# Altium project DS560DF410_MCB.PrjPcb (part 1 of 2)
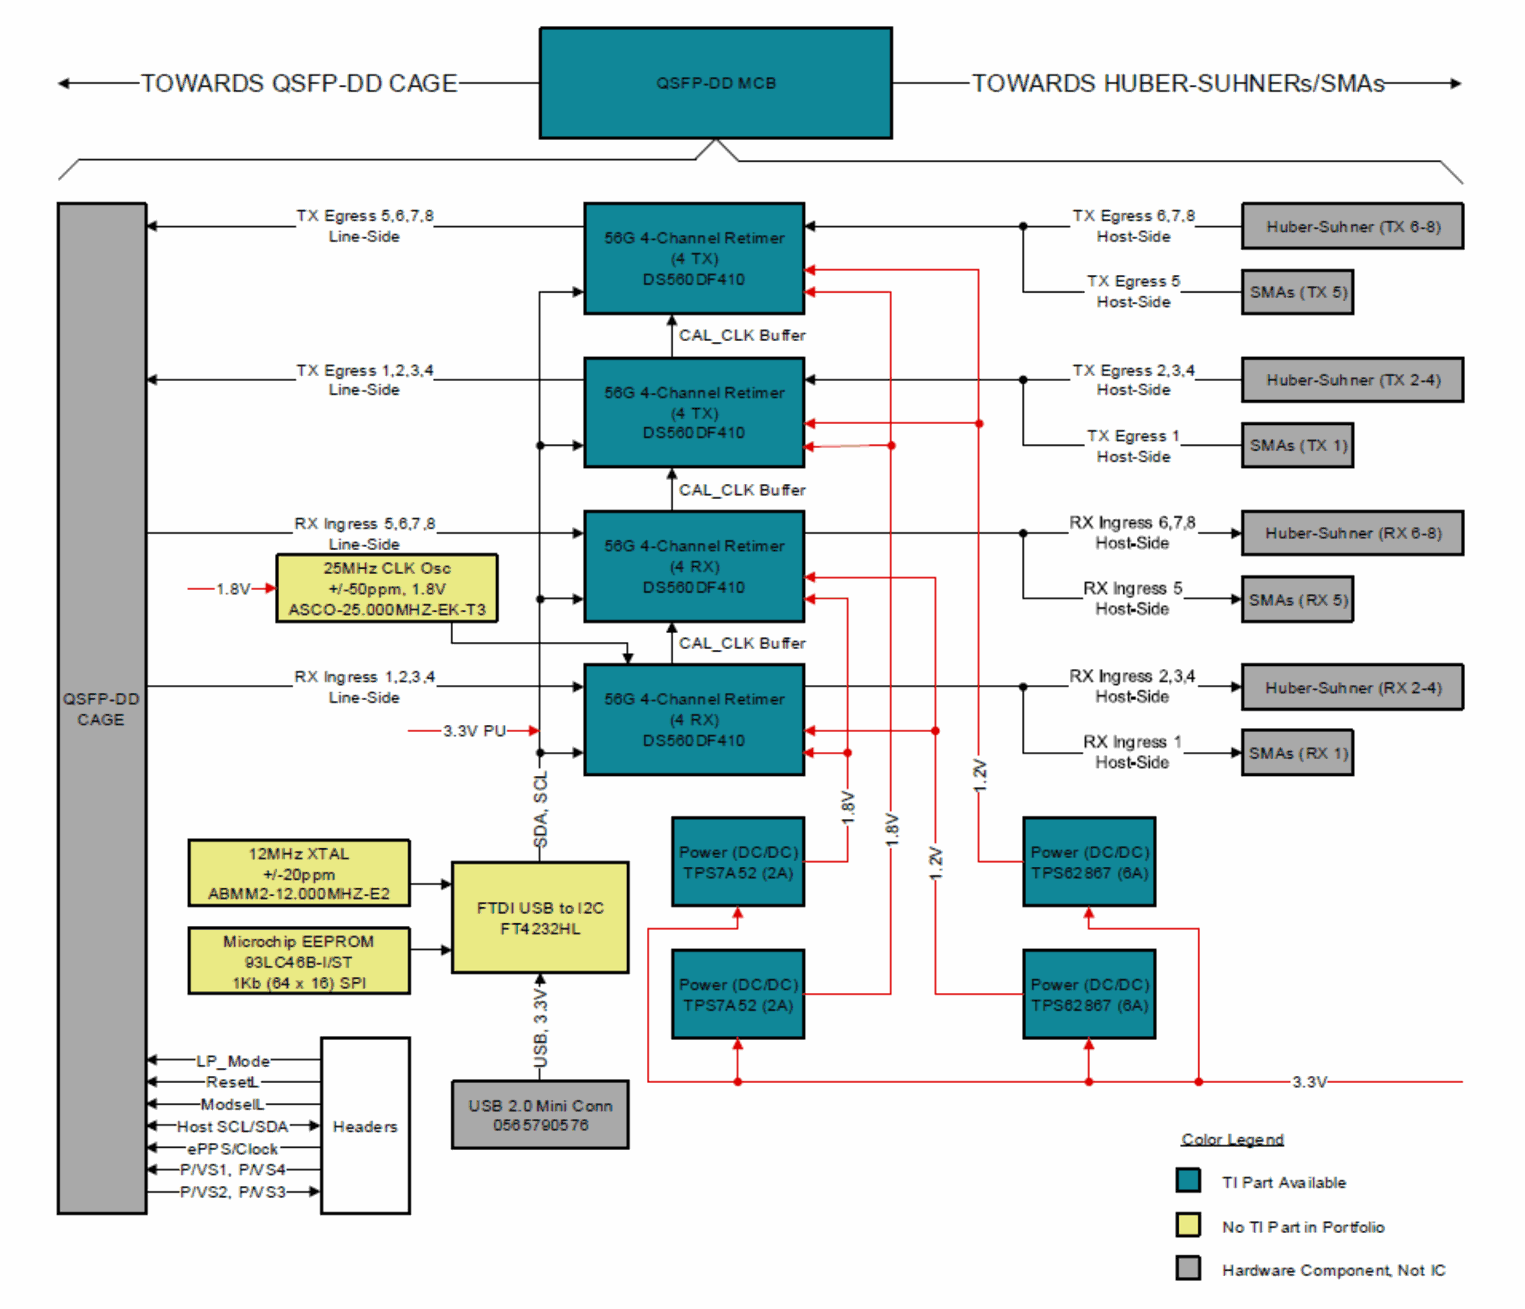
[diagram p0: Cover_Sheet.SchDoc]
CopyrightYear: 2022; PCB_Layout: TBD; PCB_Rev: E1; PRJ_Customer: Public Release; PRJ_Engineer: Lucas Wolter; PRJ_Number: TIDA-060043; PRJ_Title: 56G Retimer MCB QSFP-DD Ref Design; SCH_Rev: E1; TechSupport: http://www.ti.com/support; TID: N/A
9 sheets, 298 parts. Net scope: global (net labels, ports and power ports of the same name join across sheets).
Board file: DS560DF410_MCB_PCB_111722.PcbDoc
Sheets:
  Cover_Sheet.SchDoc
  FTDI_USB.SchDoc
  PWR_Supplies.SchDoc
  DF410_Ingress_1.SchDoc
  DF410_Ingress_2.SchDoc
  DF410_Egress_3.SchDoc
  DF410_Egress_4.SchDoc
  QSFP-DD_Connector.SchDoc
  Hardware.SchDoc

## Sheet Cover_Sheet.SchDoc: Cover Sheet
size A2; Date: Not shown in title block; ApprovedBy: Not shown in title block; CheckedBy: Not shown in title block; Author: Not shown in title block; CompanyName: Not shown in title block; Engineer: Not shown in title block; Organization: Not shown in title block; Address1: Not shown in title block; Address2: Not shown in title block; Address3: Not shown in title block; Address4: Not shown in title block; DocumentNumber: 1; Revision: Use project parameter SCH_Rev; SheetNumber: 1; SheetTotal: 1; PageSetup: Record=PageOptions¦CenterHorizontal=True¦CenterVertical=True¦PrintScale=0.69¦XCorrection=1.00¦YCorrection=1.00¦PrintKind=0¦BorderSize=5000000¦LeftOffset=0¦BottomOffset=0¦Orientation=2¦PaperLength=1000¦PaperWidth=1000¦Scale=100¦PaperSource=15¦PrintQuality=600¦MediaType=1¦DitherType=10¦PaperKind=Letter¦PrintScaleMode=1

## Sheet FTDI_USB.SchDoc: FTDI Chip, USB
size A2; Date: Not shown in title block; ApprovedBy: Not shown in title block; CheckedBy: Not shown in title block; Author: Not shown in title block; CompanyName: Not shown in title block; Engineer: Not shown in title block; Organization: Not shown in title block; Address1: Not shown in title block; Address2: Not shown in title block; Address3: Not shown in title block; Address4: Not shown in title block; DocumentNumber: 1; Revision: Use project parameter SCH_Rev; SheetNumber: 1; SheetTotal: 1; PageSetup: Record=PageOptions¦CenterHorizontal=True¦CenterVertical=True¦PrintScale=0.69¦XCorrection=1.00¦YCorrection=1.00¦PrintKind=0¦BorderSize=5000000¦LeftOffset=0¦BottomOffset=0¦Orientation=2¦PaperLength=1000¦PaperWidth=1000¦Scale=100¦PaperSource=15¦PrintQuality=600¦MediaType=1¦DitherType=10¦PaperKind=Letter¦PrintScaleMode=1
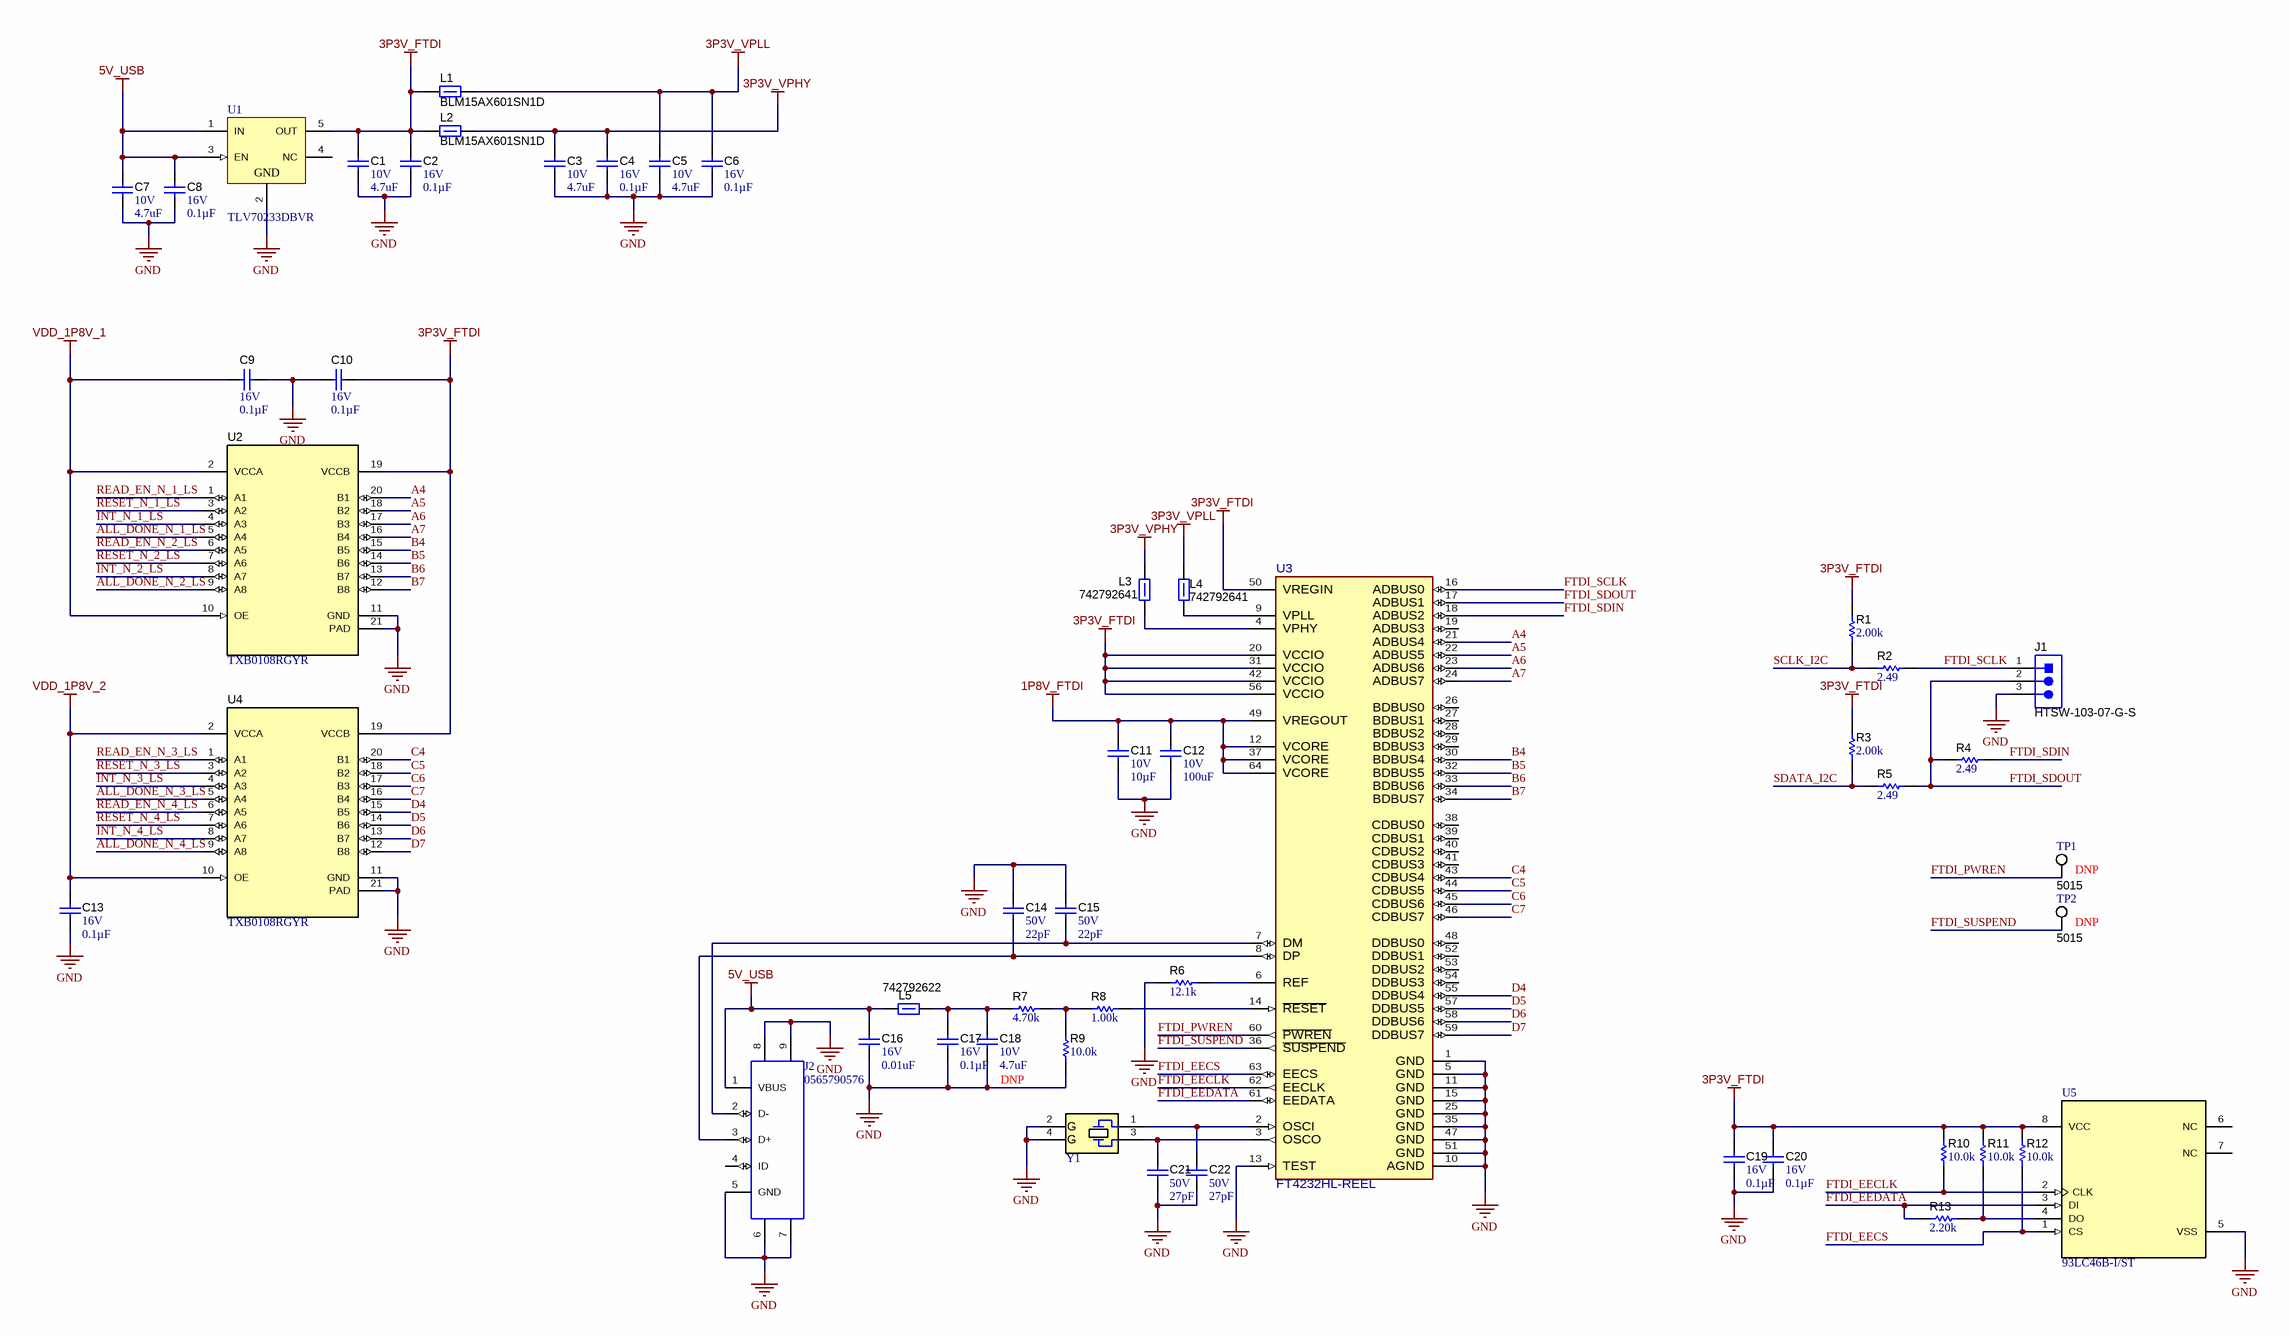
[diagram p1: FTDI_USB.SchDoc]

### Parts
C1  VDC_V: 10V  ValueDisplayed: 4.7uF  [0402_065]  (hidden comment: C1005X5R1A475K050BC)
C2  VDC_V: 16V  ValueDisplayed: 0.1µF  [0402]  (hidden comment: EMK105B7104KV-F)
C3  VDC_V: 10V  ValueDisplayed: 4.7uF  [0402_065]  (hidden comment: C1005X5R1A475K050BC)
C4  VDC_V: 16V  ValueDisplayed: 0.1µF  [0402]  (hidden comment: EMK105B7104KV-F)
C5  VDC_V: 10V  ValueDisplayed: 4.7uF  [0402_065]  (hidden comment: C1005X5R1A475K050BC)
C6  VDC_V: 16V  ValueDisplayed: 0.1µF  [0402]  (hidden comment: EMK105B7104KV-F)
C7  VDC_V: 10V  ValueDisplayed: 4.7uF  [0402_065]  (hidden comment: C1005X5R1A475K050BC)
C8  VDC_V: 16V  ValueDisplayed: 0.1µF  [0402]  (hidden comment: EMK105B7104KV-F)
C9  VDC_V: 16V  ValueDisplayed: 0.1µF  [0402]  (hidden comment: EMK105B7104KV-F)
C10  VDC_V: 16V  ValueDisplayed: 0.1µF  [0402]  (hidden comment: EMK105B7104KV-F)
C11  VDC_V: 10V  ValueDisplayed: 10µF  [0402_090]  (hidden comment: CL05A106MP8NUB8)
C12  VDC_V: 10V  ValueDisplayed: 100uF  [1206_190]  (hidden comment: C3216X5R1A107M160AC)
C13  VDC_V: 16V  ValueDisplayed: 0.1µF  [0402]  (hidden comment: EMK105B7104KV-F)
C14  VDC_V: 50V  ValueDisplayed: 22pF  [0402]  (hidden comment: GRM1555C1H220JA01D)
C15  VDC_V: 50V  ValueDisplayed: 22pF  [0402]  (hidden comment: GRM1555C1H220JA01D)
C16  VDC_V: 16V  ValueDisplayed: 0.01uF  [0402]  (hidden comment: GRM155R61C103KA01D)
C17  VDC_V: 16V  ValueDisplayed: 0.1µF  [0402]  (hidden comment: EMK105B7104KV-F)
C18  VDC_V: 10V  ValueDisplayed: 4.7uF  [0402_065]  (hidden comment: C1005X5R1A475K050BC)
C19  VDC_V: 16V  ValueDisplayed: 0.1µF  [0402]  (hidden comment: EMK105B7104KV-F)
C20  VDC_V: 16V  ValueDisplayed: 0.1µF  [0402]  (hidden comment: EMK105B7104KV-F)
C21  VDC_V: 50V  ValueDisplayed: 27pF  [0402]  (hidden comment: GJM1555C1H270JB01)
C22  VDC_V: 50V  ValueDisplayed: 27pF  [0402]  (hidden comment: GJM1555C1H270JB01)
J1  HTSW-103-07-G-S  [Samtec_HTSW-103-07-G-S]
J2  0565790576  [Molex_0565790576]
L1  BLM15AX601SN1D  [0402]
L2  BLM15AX601SN1D  [0402]
L3  742792641  [0603]
L4  742792641  [0603]
L5  742792622  [0603]
R1  ValueDisplayed: 2.00k  [0402]  (hidden comment: ERJ-2RKF2001X)
R2  ValueDisplayed: 2.49  [0402]  (hidden comment: CRCW04022R49FKED)
R3  ValueDisplayed: 2.00k  [0402]  (hidden comment: ERJ-2RKF2001X)
R4  ValueDisplayed: 2.49  [0402]  (hidden comment: CRCW04022R49FKED)
R5  ValueDisplayed: 2.49  [0402]  (hidden comment: CRCW04022R49FKED)
R6  ValueDisplayed: 12.1k  [0402]  (hidden comment: CRCW040212K1FKED)
R7  ValueDisplayed: 4.70k  [0402]  (hidden comment: ERJ-2RKF4701X)
R8  ValueDisplayed: 1.00k  [0402]  (hidden comment: CRCW04021K00FKED)
R9  ValueDisplayed: 10.0k  [0402]  (hidden comment: PCF0402-12-10K0BT1)
R10  ValueDisplayed: 10.0k  [0402]  (hidden comment: PCF0402-12-10K0BT1)
R11  ValueDisplayed: 10.0k  [0402]  (hidden comment: PCF0402-12-10K0BT1)
R12  ValueDisplayed: 10.0k  [0402]  (hidden comment: PCF0402-12-10K0BT1)
R13  ValueDisplayed: 2.20k  [0402]  (hidden comment: ERA2AEB222X)
TP1  5015  [Testpoint_Keystone_Miniature]
TP2  5015  [Testpoint_Keystone_Miniature]
U1  TLV70233DBVR  [DBV0005A_N]
U2  TXB0108RGYR  [RGY0020A]
U3  FT4232HL-REEL  [FP-FT4232HL-REEL_LQFP64-MFG]
U4  TXB0108RGYR  [RGY0020A]
U5  93LC46B-I/ST  [TSSOP-8]
Y1  ABMM2-12.000MHZ-E2-T  [Abracon_ABMM2]  (value not drawn)

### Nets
1P8V_FTDI: C11.1 C12.1 U3.12(VCORE) U3.37(VCORE) U3.49(VREGOUT) U3.64(VCORE)
3P3V_FTDI: C1.1 C2.1 C10.2 C19.1 C20.1 L1.1 L2.1 R1.2 R3.2 R10.2 R11.2 R12.2 U1.5(OUT) U2.19(VCCB) U3.20(VCCIO) U3.31(VCCIO) U3.42(VCCIO) U3.50(VREGIN) U3.56(VCCIO) U4.19(VCCB) U5.8(VCC)
3P3V_VPHY: C3.1 C4.1 L2.2 L3.2
3P3V_VPLL: C5.1 C6.1 L1.2 L4.2
5V_USB: C7.1 C8.1 C16.1 J2.1(VBUS) L5.1 U1.1(IN) U1.3(EN)
GND: C1.2 C2.2 C3.2 C4.2 C5.2 C6.2 C7.2 C8.2 C9.2 C10.1 C11.2 C12.2 C13.1 C14.1 C15.1 C16.2 C17.2 C18.2 C19.2 C20.2 C21.2 C22.2 J1.3 J2.5(GND) J2.6 J2.7 J2.8 J2.9 R6.1 R9.1 U1.2(GND) U2.11(GND) U2.21(PAD) U3.1(GND) U3.5(GND) U3.10(AGND) U3.11(GND) U3.13(TEST) U3.15(GND) U3.25(GND) U3.35(GND) U3.47(GND) U3.51(GND) U4.11(GND) U4.21(PAD) U5.5(VSS) Y1.2(GND) Y1.4(GND)
VDD_1P8V_1: C9.1 U2.2(VCCA) U2.10(OE)
VDD_1P8V_2: C13.2 U4.2(VCCA) U4.10(OE)
A4: U2.20(B1) U3.21(ADBUS4)
A5: U2.18(B2) U3.22(ADBUS5)
A6: U2.17(B3) U3.23(ADBUS6)
A7: U2.16(B4) U3.24(ADBUS7)
ALL_DONE_N_1_LS: U2.5(A4)
ALL_DONE_N_2_LS: U2.9(A8)
ALL_DONE_N_3_LS: U4.5(A4)
ALL_DONE_N_4_LS: U4.9(A8)
B4: U2.15(B5) U3.30(BDBUS4)
B5: U2.14(B6) U3.32(BDBUS5)
B6: U2.13(B7) U3.33(BDBUS6)
B7: U2.12(B8) U3.34(BDBUS7)
C4: U3.43(CDBUS4) U4.20(B1)
C5: U3.44(CDBUS5) U4.18(B2)
C6: U3.45(CDBUS6) U4.17(B3)
C7: U3.46(CDBUS7) U4.16(B4)
D4: U3.55(DDBUS4) U4.15(B5)
D5: U3.57(DDBUS5) U4.14(B6)
D6: U3.58(DDBUS6) U4.13(B7)
D7: U3.59(DDBUS7) U4.12(B8)
FTDI_EECLK: R10.1 U3.62(EECLK) U5.2(CLK)
FTDI_EECS: R12.1 U3.63(EECS) U5.1(CS)
FTDI_EEDATA: R13.1 U3.61(EEDATA) U5.3(DI)
FTDI_PWREN: TP1.1 U3.60(~{PWREN})
FTDI_SCLK: J1.1 R2.2 U3.16(ADBUS0)
FTDI_SDIN: R4.2 U3.18(ADBUS2)
FTDI_SDOUT: J1.2 R4.1 R5.2 U3.17(ADBUS1)
FTDI_SUSPEND: TP2.1 U3.36(~{SUSPEND})
INT_N_1_LS: U2.4(A3)
INT_N_2_LS: U2.8(A7)
INT_N_3_LS: U4.4(A3)
INT_N_4_LS: U4.8(A7)
READ_EN_N_1_LS: U2.1(A1)
READ_EN_N_2_LS: U2.6(A5)
READ_EN_N_3_LS: U4.1(A1)
READ_EN_N_4_LS: U4.6(A5)
RESET_N_1_LS: U2.3(A2)
RESET_N_2_LS: U2.7(A6)
RESET_N_3_LS: U4.3(A2)
RESET_N_4_LS: U4.7(A6)
SCLK_I2C: R1.1 R2.1
SDATA_I2C: R3.1 R5.1
NetC14_2: C14.2 J2.3(D+) U3.8(DP)
NetC15_2: C15.2 J2.2(D-) U3.7(DM)
NetC17_1: C17.1 C18.1 L5.2 R7.1
NetC21_1: C21.1 U3.3(OSCO) Y1.3
NetC22_1: C22.1 U3.2(OSCI) Y1.1
NetL3_1: L3.1 U3.4(VPHY)
NetL4_1: L4.1 U3.9(VPLL)
NetR6_2: R6.2 U3.6(REF)
NetR7_2: R7.2 R8.1 R9.2
NetR8_2: R8.2 U3.14(~{RESET})
NetR11_1: R11.1 R13.2 U5.4(DO)

Not connected (* = marked no-connect by the designer): J2 4(ID); U1 4(NC); U3 19(ADBUS3) 26(BDBUS0) 27(BDBUS1) 28(BDBUS2) 29(BDBUS3) 38(CDBUS0) 39(CDBUS1) 40(CDBUS2) 41(CDBUS3) 48(DDBUS0) 52(DDBUS1) 53(DDBUS2) 54(DDBUS3); U5 6(NC) 7(NC)

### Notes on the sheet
- (near TP1) DNP
- (near TP2) DNP
- (near C18) DNP

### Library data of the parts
C1 C3 C5 C7 C18 = CMP-0006268-2: CAP, CERM, 4.7 uF, 10 V, +/- 10%, X5R, 0402; Manufacturer: TDK; TaMin_C: -55°C; ESR_ohm: 3.417m; Polarized: N; SizeAreaWB_mm2: 3; Value1: 0.003417 ohm; U/M: EA; Value: 4.7uF; TaMax_C: 85°C; SizeZ_mm: 0.65; SizeX_mm: 1; SizeY_mm: 0.5; Cap_F: 4.7µF; IRMS_A: 2.7063A; AEC Category: Q200
C2 C4 C6 C8-C10 C13 C17 C19 C20 = CMP-0860188-1: CAP, CERM, 0.1 µF, 16 V,+/- 10%, X7R, 0402; Manufacturer: Taiyo Yuden; TaMin_C: -55°C; Polarized: N; SizeAreaWB_mm2: 3; U/M: EA; Value: 0.1uF; TaMax_C: 125°C; SizeZ_mm: 0.6; SizeX_mm: 1; SizeY_mm: 0.5; Cap_F: 100nF; AEC Category: Q200
C11 = CMP-0084009-1: CAP, CERM, 10 µF, 10 V,+/- 20%, X5R, 0402; Manufacturer: Samsung Electro-Mechanics; TaMin_C: -55°C; ESR_ohm: 1m; Polarized: N; Green_Lifecycle: Active; SizeAreaWB_mm2: 3; Green_REACh: Passed; Value1: 0.001 ohm; U/M: EA; Value: 10uF; TaMax_C: 85°C; SizeZ_mm: 0.9; SizeX_mm: 1; SizeY_mm: 0.5; Cap_Case: 0402; AEC Category: Q200
C12 = CMP-0008649-2: CAP, CERM, 100 uF, 10 V, +/- 20%, X5R, 1206_190; Manufacturer: TDK; TaMin_C: -55°C; ESR_ohm: 2.838m; Polarized: N; SizeAreaWB_mm2: 10.92; Value1: 0.002838 ohm; U/M: EA; Value: 100uF; TaMax_C: 85°C; SizeZ_mm: 1.9; SizeX_mm: 3.2; SizeY_mm: 1.6; SizeArea_mm2: 5.12; Cap_F: 100µF; IRMS_A: 4.3069A; AEC Category: Q200
C14 C15 = CMP-0006439-2: CAP, CERM, 22 pF, 50 V, +/- 5%, C0G/NP0, 0402; Manufacturer: MuRata; TaMin_C: -55°C; Polarized: N; SizeAreaWB_mm2: 3; Value1: Unknown; U/M: EA; Value: 22pF; TaMax_C: 125°C; SizeZ_mm: 0.6; SizeX_mm: 1; SizeY_mm: 0.5; AEC Category: Q200
C16 = CMP-0006590-2: CAP, CERM, 0.01 uF, 16 V, +/- 10%, X5R, 0402; Manufacturer: MuRata; TaMin_C: -55°C; Polarized: N; SizeAreaWB_mm2: 3; Value1: Unknown; U/M: EA; Value: 0.01uF; TaMax_C: 85°C; SizeZ_mm: 0.6; SizeX_mm: 1; SizeY_mm: 0.5; Cap_F: 10nF; AEC Category: Q200
C21 C22 = CMP-0006365-2: CAP, CERM, 27 pF, 50 V, +/- 5%, C0G/NP0, 0402; Manufacturer: MuRata; TaMin_C: -55°C; Polarized: N; SizeAreaWB_mm2: 3; Value1: Unknown; U/M: EA; Value: 27pF; TaMax_C: 125°C; SizeZ_mm: 0.6; SizeX_mm: 1; SizeY_mm: 0.5; AEC Category: Q200
J1 = CMP-0075484-1: Header, 100mil, 3x1, Gold, TH; Manufacturer: Samtec; Green_REACh: Passed; CT: False; Green_Lifecycle: Active; CNHeader: True
J2 = CMP-0079047-2: Receptacle, USB Mini-AB, 0.8mm, 5x1, Gold, R/A, SMT; Manufacturer: Molex; Cert_UL: Y; Gender: Female; Pitch_mm: 0.8; Row_Count: 1; Current_A: 1A; Voltage_V: 30V
L1 L2 = CMP-0003317-1: Ferrite Bead, 600 ohm @ 100 MHz, 0.5 A, 0402; Manufacturer: MuRata; ZTyp@100MHz_Ohm: 600; SizeAreaWB_mm2: 3; DCR_ohm: 0.34; Value1: 0.34 ohm; Value: 600 ohm; Imax_A: 500mA; SizeZ_mm: 0.6; SizeX_mm: 1; SizeY_mm: 0.5; Value2: 0.5A
L3 L4 = CMP-0003192-2: Ferrite Bead, 300 ohm @ 100 MHz, 2 A, 0603; Manufacturer: Wurth Elektronik; Ztyp@1GHz_Ohm: 273.989; ZTyp@100MHz_Ohm: 300; SizeAreaWB_mm2: 4.68; DCR_ohm: 0.15; Value1: 0.15 ohm; Value: 300 ohm; Imax_A: 2A; SizeZ_mm: 1; SizeX_mm: 1.6; SizeY_mm: 0.8; SizeArea_mm2: 1.28
L5 = CMP-0003185-2: Ferrite Bead, 180 ohm @ 100 MHz, 0.5 A, 0603; Manufacturer: Wurth Elektronik; Ztyp@1GHz_Ohm: 190.577; ZTyp@100MHz_Ohm: 180; SizeAreaWB_mm2: 4.68; DCR_ohm: 0.3; Value1: 0.3 ohm; Value: 180 ohm; Imax_A: 500mA; SizeZ_mm: 1; SizeX_mm: 1.6; SizeY_mm: 0.8; Value2: 0.5A; SizeArea_mm2: 1.28
R1 R3 = CMP-0026676-1: RES, 2.00 k, 1%, 0.1 W, AEC-Q200 Grade 0, 0402; Manufacturer: Panasonic; Power_W: 100mW; TempCo: 100 ppm/C; Value_Code: 2k00; U/M: EA; Value: 2.00k; EIA_Code: E96; Res_ohm: 2k; SizeX_mm: 1; SizeY_mm: 0.5; SizeZ_mm: 0.6; Value2: 0.1W; AEC Qualified: Y; VDC_V: 50V; AEC Grade: 0; AEC Category: Q200
R2 R4 R5 = CMP-0026271-2: RES, 2.49, 1%, 0.063 W, AEC-Q200 Grade 0, 0402; Manufacturer: Vishay-Dale; Power_W: 63mW; TempCo: 100 ppm/C; Value_Code: 2R49; Value: 2.49; EIA_Code: E96; SizeX_mm: 1; SizeY_mm: 0.5; SizeZ_mm: 0.6; Value2: 0.063W; AEC Qualified: Y; VDC_V: 50V; AEC Category: Q200; AEC Grade: 0
R6 = CMP-0025991-3: RES, 12.1 k, 1%, 0.063 W, AEC-Q200 Grade 0, 0402; Manufacturer: Vishay-Dale; Power_W: 63mW; TempCo: 100 ppm/C; Value_Code: 12k1; Value: 12.1k; EIA_Code: E96; SizeX_mm: 1; SizeY_mm: 0.5; SizeZ_mm: 0.6; Value2: 0.063W; AEC Qualified: Y; VDC_V: 50V; AEC Category: Q200; AEC Grade: 0
R7 = CMP-0026700-1: RES, 4.70 k, 1%, 0.1 W, 0402; Manufacturer: Panasonic; Power_W: 100mW; TempCo: 100 ppm/C; Value_Code: 4k70; U/M: EA; Value: 4.70k; Res_ohm: 4.7k; SizeX_mm: 1; SizeY_mm: 0.5; SizeZ_mm: 0.6; Value2: 0.1W; VDC_V: 50V; AEC Category: Q200
R8 = CMP-0026071-3: RES, 1.00 k, 1%, 0.063 W, AEC-Q200 Grade 0, 0402; Manufacturer: Vishay-Dale; Power_W: 63mW; TempCo: 100 ppm/C; Value_Code: 1k00; Value: 1.00k; EIA_Code: E96; Res_ohm: 1k; SizeX_mm: 1; SizeY_mm: 0.5; SizeZ_mm: 0.6; Value2: 0.063W; AEC Qualified: Y; VDC_V: 50V; AEC Category: Q200; AEC Grade: 0
R9-R12 = CMP-0026796-1: RES, 10.0 k, 0.1%, 0.063 W, 0402; Manufacturer: TT Electronics/IRC; Power_W: 63mW; TempCo: 10 ppm/C; Value_Code: 10k0; U/M: EA; Value: 10.0k; EIA_Code: E192; Res_ohm: 10k; SizeX_mm: 1; SizeY_mm: 0.5; SizeZ_mm: 0.6; Value2: 0.063W; AEC Qualified: N; VDC_V: 25V; AEC Category: Q200
R13 = CMP-0074667-1: RES, 2.20 k, 0.1%, 0.0625 W, AEC-Q200 Grade 0, 0402; Manufacturer: Panasonic; Power_W: 62.5mW; TempCo: 25 ppm/C; Value_Code: 2k20; U/M: EA; Value: 2.20k; Res_ohm: 2.2k; SizeX_mm: 1.0; SizeY_mm: 0.5; SizeZ_mm: 0.6; AEC Qualified: Y; VDC_V: 50V; AEC Grade: 0; AEC Category: Q200
TP1 TP2 = CMP-0055152-2: Test Point, Miniature, SMT; Manufacturer: Keystone Electronics; CNHeader: FALSE; Green_Lifecycle: Active; Green_REACh: Passed; CT: TRUE
U1 = CMP-0035516-1: Single Output LDO, 300 mA, Fixed 3.3 V Output, 2 to 5.5 V Input, with Low IQ, 5-pin SOT-23 (DBV), -40 to 125 degC, Green (RoHS & no Sb/Br); Manufacturer: Texas Instruments; Fixed Output Options(V): 3.3; Vdo(Typ)(mV): 220; Accuracy(%): 2; Iq(Typ)(mA): 0.03; SubFamily: Single Channel LDO; Iout(Max)(A): 0.3; Vin(Max)(V): 5.5
U2 U4 = CMP-0074359-2: 8-Bit Bidirectional Voltage-Level Shifter with Auto Direction Sensing and +/-15-kV ESD Protect, RGY0020A (VQFN-20); Alternate Manufacturer: Texas Instruments; SizeAreaWB_mm2: 24.75; U/M: EA; SizeZ_mm: 1.0; SizeX_mm: 3.5; SizeY_mm: 4.5; SizeArea_mm2: 15.75; CompType: IC
U3 = CMP-0086897-1: IC USB HS QUAD UART/SYNC 64-LQFP; Manufacturer: FTDI; SizeZ_mm: 1.6mm
U5 = CMP-0081524-1: 1K Microwire Compatible Serial EEPROM, TSSOP-8; Manufacturer: Microchip; SizeArea_mm2: 19.2; SizeAreaWB_mm2: 42; SizeY_mm: 3; SizeZ_mm: 1.2; SizeX_mm: 6.4
Y1 = CMP-0079033-1: Crystal, 12 MHz, 20 ppm, SMD; Manufacturer: Abracon Corporation; Frequency Stability: -20 / +20 ppm; SizeAreaWB_mm2: 44.8; SizeArea_mm2: 21.6; Frequency Tolerance: 20 ppm; AEC Category: Q200; TaMax_C: 60°C; SizeZ_mm: 1.2; Frequency_Fixed: 12MHz; TaMin_C: -10°C; SizeY_mm: 6; SizeX_mm: 3.6

## Sheet PWR_Supplies.SchDoc: Power Supplies
size A2; Date: Not shown in title block; ApprovedBy: Not shown in title block; CheckedBy: Not shown in title block; Author: Not shown in title block; CompanyName: Not shown in title block; Engineer: Not shown in title block; Organization: Not shown in title block; Address1: Not shown in title block; Address2: Not shown in title block; Address3: Not shown in title block; Address4: Not shown in title block; DocumentNumber: 1; Revision: Use project parameter SCH_Rev; SheetNumber: 1; SheetTotal: 1; PageSetup: Record=PageOptions¦CenterHorizontal=True¦CenterVertical=True¦PrintScale=0.69¦XCorrection=1.00¦YCorrection=1.00¦PrintKind=0¦BorderSize=5000000¦LeftOffset=0¦BottomOffset=0¦Orientation=2¦PaperLength=1000¦PaperWidth=1000¦Scale=100¦PaperSource=15¦PrintQuality=600¦MediaType=1¦DitherType=10¦PaperKind=Letter¦PrintScaleMode=1
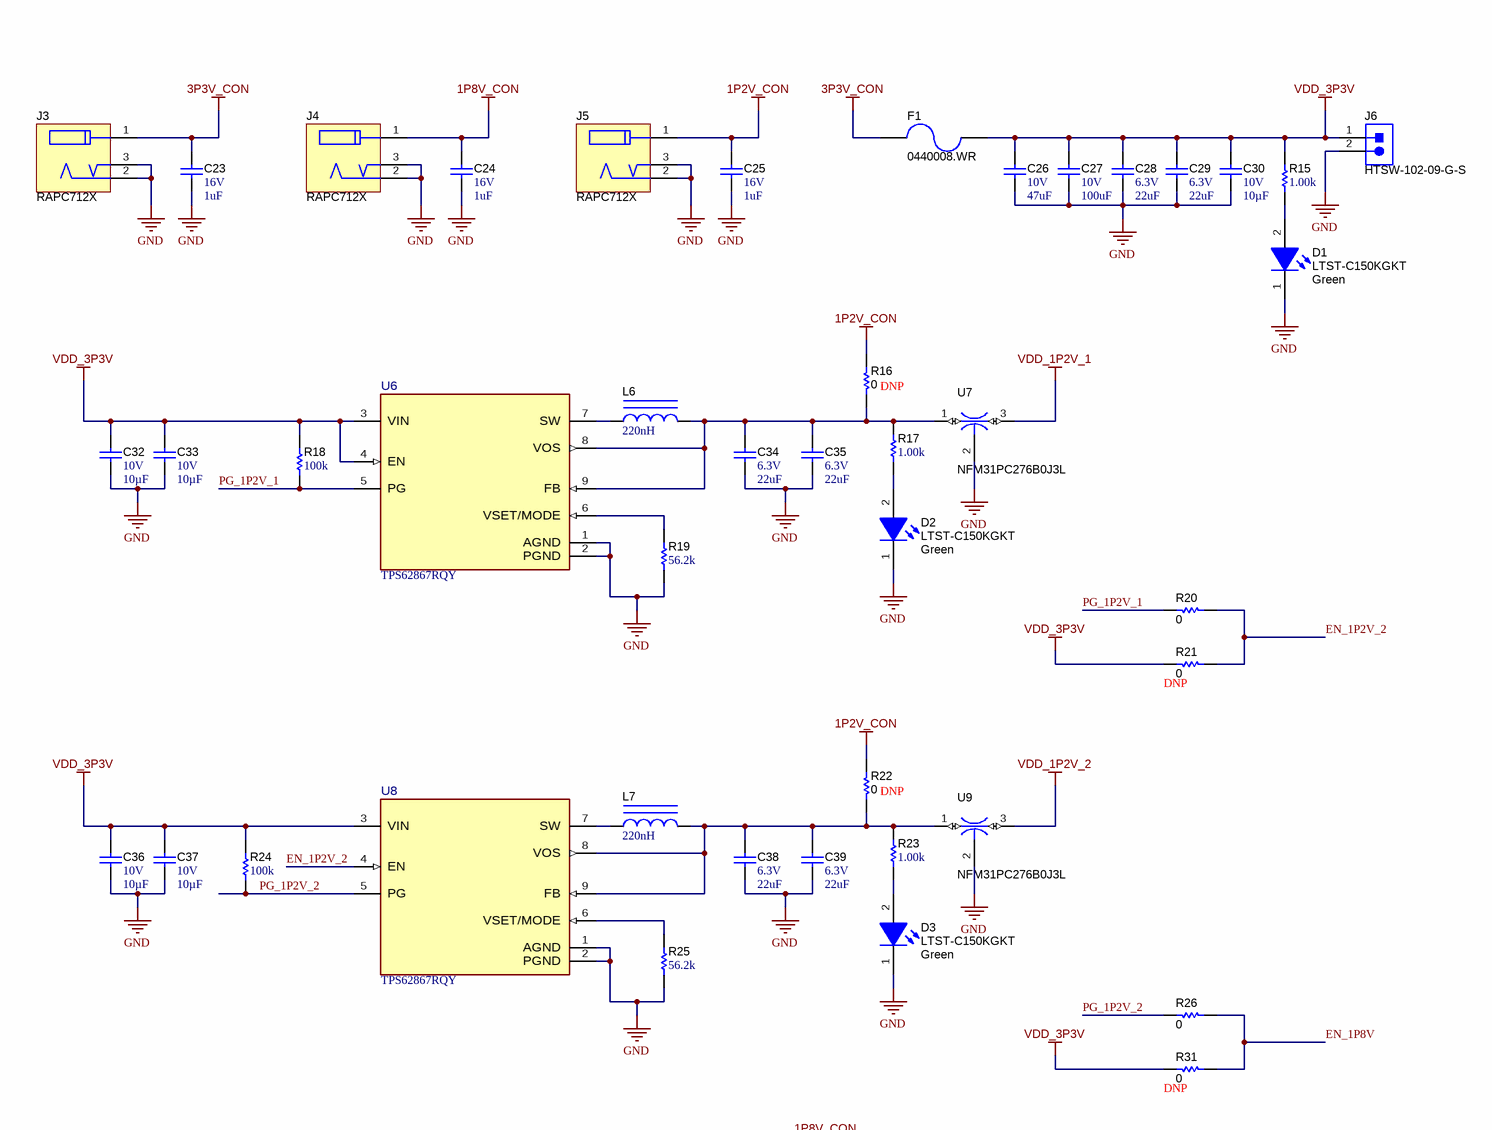
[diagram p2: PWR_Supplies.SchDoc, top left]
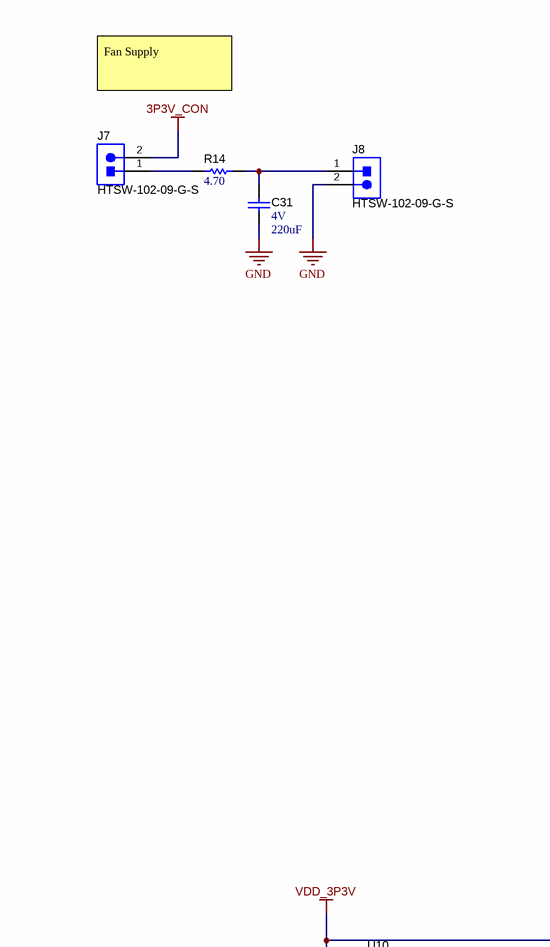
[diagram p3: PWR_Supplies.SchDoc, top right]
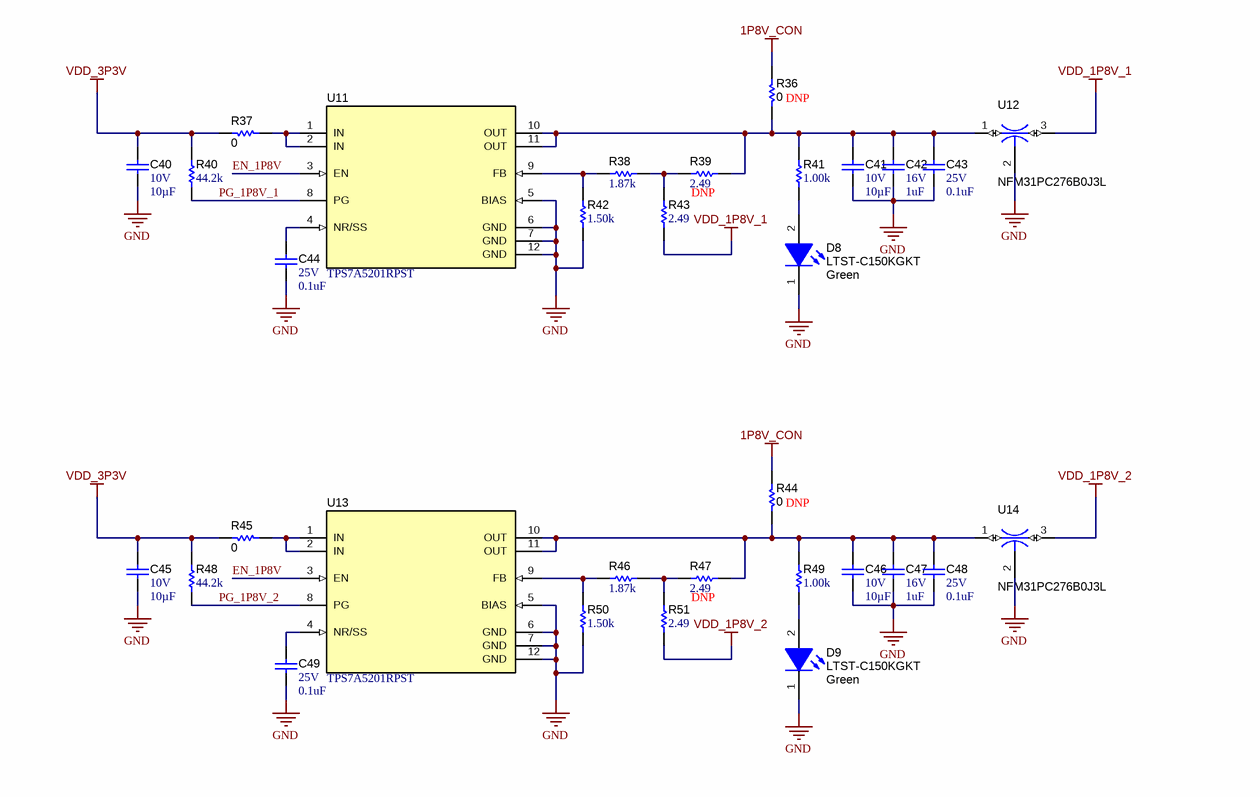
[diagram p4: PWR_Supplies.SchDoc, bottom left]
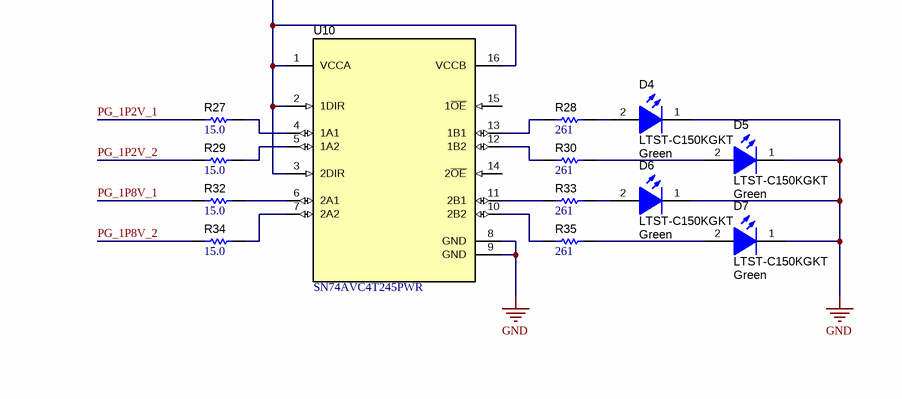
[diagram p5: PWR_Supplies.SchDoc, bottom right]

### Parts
C23  VDC_V: 16V  ValueDisplayed: 1uF  [0402]  (hidden comment: EMK105BJ105KVHF)
C24  VDC_V: 16V  ValueDisplayed: 1uF  [0402]  (hidden comment: EMK105BJ105KVHF)
C25  VDC_V: 16V  ValueDisplayed: 1uF  [0402]  (hidden comment: EMK105BJ105KVHF)
C26  VDC_V: 10V  ValueDisplayed: 47uF  [1206_180]  (hidden comment: GRT31CR61A476KE13L)
C27  VDC_V: 10V  ValueDisplayed: 100uF  [1206_190]  (hidden comment: C3216X5R1A107M160AC)
C28  VDC_V: 6.3V  ValueDisplayed: 22uF  [0402]  (hidden comment: GRM155R60J226ME11D)
C29  VDC_V: 6.3V  ValueDisplayed: 22uF  [0402]  (hidden comment: GRM155R60J226ME11D)
C30  VDC_V: 10V  ValueDisplayed: 10µF  [0402_090]  (hidden comment: CL05A106MP8NUB8)
C31  VDC_V: 4V  ValueDisplayed: 220uF  [1206_190]  (hidden comment: GRM31CR60G227ME11L)
C32  VDC_V: 10V  ValueDisplayed: 10µF  [0402_090]  (hidden comment: CL05A106MP8NUB8)
C33  VDC_V: 10V  ValueDisplayed: 10µF  [0402_090]  (hidden comment: CL05A106MP8NUB8)
C34  VDC_V: 6.3V  ValueDisplayed: 22uF  [0402]  (hidden comment: GRM155R60J226ME11D)
C35  VDC_V: 6.3V  ValueDisplayed: 22uF  [0402]  (hidden comment: GRM155R60J226ME11D)
C36  VDC_V: 10V  ValueDisplayed: 10µF  [0402_090]  (hidden comment: CL05A106MP8NUB8)
C37  VDC_V: 10V  ValueDisplayed: 10µF  [0402_090]  (hidden comment: CL05A106MP8NUB8)
C38  VDC_V: 6.3V  ValueDisplayed: 22uF  [0402]  (hidden comment: GRM155R60J226ME11D)
C39  VDC_V: 6.3V  ValueDisplayed: 22uF  [0402]  (hidden comment: GRM155R60J226ME11D)
C40  VDC_V: 10V  ValueDisplayed: 10µF  [0402_090]  (hidden comment: CL05A106MP8NUB8)
C41  VDC_V: 10V  ValueDisplayed: 10µF  [0402_090]  (hidden comment: CL05A106MP8NUB8)
C42  VDC_V: 16V  ValueDisplayed: 1uF  [0402]  (hidden comment: EMK105BJ105KVHF)
C43  VDC_V: 25V  ValueDisplayed: 0.1uF  [0402]  (hidden comment: GRM155R71E104KE14D)
C44  VDC_V: 25V  ValueDisplayed: 0.1uF  [0402]  (hidden comment: GRM155R71E104KE14D)
C45  VDC_V: 10V  ValueDisplayed: 10µF  [0402_090]  (hidden comment: CL05A106MP8NUB8)
C46  VDC_V: 10V  ValueDisplayed: 10µF  [0402_090]  (hidden comment: CL05A106MP8NUB8)
C47  VDC_V: 16V  ValueDisplayed: 1uF  [0402]  (hidden comment: EMK105BJ105KVHF)
C48  VDC_V: 25V  ValueDisplayed: 0.1uF  [0402]  (hidden comment: GRM155R71E104KE14D)
C49  VDC_V: 25V  ValueDisplayed: 0.1uF  [0402]  (hidden comment: GRM155R71E104KE14D)
D1  LTST-C150KGKT  value Green  [LTST-C150_1206_Green]
D2  LTST-C150KGKT  value Green  [LTST-C150_1206_Green]
D3  LTST-C150KGKT  value Green  [LTST-C150_1206_Green]
D4  LTST-C150KGKT  value Green  [LTST-C150_1206_Green]
D5  LTST-C150KGKT  value Green  [LTST-C150_1206_Green]
D6  LTST-C150KGKT  value Green  [LTST-C150_1206_Green]
D7  LTST-C150KGKT  value Green  [LTST-C150_1206_Green]
D8  LTST-C150KGKT  value Green  [LTST-C150_1206_Green]
D9  LTST-C150KGKT  value Green  [LTST-C150_1206_Green]
F1  0440008.WR  [1206]
J3  RAPC712X  [CONN_RAPC712X]
J4  RAPC712X  [CONN_RAPC712X]
J5  RAPC712X  [CONN_RAPC712X]
J6  HTSW-102-09-G-S  [Samtec_HTSW-102-09-x-S]
J7  HTSW-102-09-G-S  [Samtec_HTSW-102-09-x-S]
J8  HTSW-102-09-G-S  [Samtec_HTSW-102-09-x-S]
L6  ValueDisplayed: 220nH  [744373210022]  (hidden comment: 744373210022)
L7  ValueDisplayed: 220nH  [744373210022]  (hidden comment: 744373210022)
R14  ValueDisplayed: 4.70  [0201]  (hidden comment: RC0201FR-074R7L)
R15  ValueDisplayed: 1.00k  [0402]  (hidden comment: MCR01MZPF1001)
R16  ValueDisplayed: 0  [0402]  (hidden comment: ERJ-2GE0R00X)
R17  ValueDisplayed: 1.00k  [0402]  (hidden comment: MCR01MZPF1001)
R18  ValueDisplayed: 100k  [0402]  (hidden comment: RC0402FR-07100KL)
R19  ValueDisplayed: 56.2k  [0402]  (hidden comment: CRCW040256K2FKED)
R20  ValueDisplayed: 0  [0402]  (hidden comment: ERJ-2GE0R00X)
R21  ValueDisplayed: 0  [0402]  (hidden comment: ERJ-2GE0R00X)
R22  ValueDisplayed: 0  [0402]  (hidden comment: ERJ-2GE0R00X)
R23  ValueDisplayed: 1.00k  [0402]  (hidden comment: MCR01MZPF1001)
R24  ValueDisplayed: 100k  [0402]  (hidden comment: RC0402FR-07100KL)
R25  ValueDisplayed: 56.2k  [0402]  (hidden comment: CRCW040256K2FKED)
R26  ValueDisplayed: 0  [0402]  (hidden comment: ERJ-2GE0R00X)
R27  ValueDisplayed: 15.0  [0402]  (hidden comment: CRCW040215R0FKED)
R28  ValueDisplayed: 261  [0402]  (hidden comment: CRCW0402261RFKED)
R29  ValueDisplayed: 15.0  [0402]  (hidden comment: CRCW040215R0FKED)
R30  ValueDisplayed: 261  [0402]  (hidden comment: CRCW0402261RFKED)
R31  ValueDisplayed: 0  [0402]  (hidden comment: ERJ-2GE0R00X)
R32  ValueDisplayed: 15.0  [0402]  (hidden comment: CRCW040215R0FKED)
R33  ValueDisplayed: 261  [0402]  (hidden comment: CRCW0402261RFKED)
R34  ValueDisplayed: 15.0  [0402]  (hidden comment: CRCW040215R0FKED)
R35  ValueDisplayed: 261  [0402]  (hidden comment: CRCW0402261RFKED)
R36  ValueDisplayed: 0  [0402]  (hidden comment: ERJ-2GE0R00X)
R37  ValueDisplayed: 0  [0402]  (hidden comment: ERJ-2GE0R00X)
R38  ValueDisplayed: 1.87k  [0402]  (hidden comment: RC0402FR-071K87L)
R39  ValueDisplayed: 2.49  [0402]  (hidden comment: CRCW04022R49FKED)
R40  ValueDisplayed: 44.2k  [0402]  (hidden comment: CRCW040244K2FKED)
R41  ValueDisplayed: 1.00k  [0402]  (hidden comment: MCR01MZPF1001)
R42  ValueDisplayed: 1.50k  [0402]  (hidden comment: CRCW04021K50FKED)
R43  ValueDisplayed: 2.49  [0402]  (hidden comment: CRCW04022R49FKED)
R44  ValueDisplayed: 0  [0402]  (hidden comment: ERJ-2GE0R00X)
R45  ValueDisplayed: 0  [0402]  (hidden comment: ERJ-2GE0R00X)
R46  ValueDisplayed: 1.87k  [0402]  (hidden comment: RC0402FR-071K87L)
R47  ValueDisplayed: 2.49  [0402]  (hidden comment: CRCW04022R49FKED)
R48  ValueDisplayed: 44.2k  [0402]  (hidden comment: CRCW040244K2FKED)
R49  ValueDisplayed: 1.00k  [0402]  (hidden comment: MCR01MZPF1001)
R50  ValueDisplayed: 1.50k  [0402]  (hidden comment: CRCW04021K50FKED)
R51  ValueDisplayed: 2.49  [0402]  (hidden comment: CRCW04022R49FKED)
U6  TPS62867RQY  [RQY0009A-MFG]
U7  NFM31PC276B0J3L  [Murata_NFM31P]
U8  TPS62867RQY  [RQY0009A-MFG]
U9  NFM31PC276B0J3L  [Murata_NFM31P]
U10  SN74AVC4T245PWR  [PW0016A_N]
U11  TPS7A5201RPST  [RPS0012A]
U12  NFM31PC276B0J3L  [Murata_NFM31P]
U13  TPS7A5201RPST  [RPS0012A]
U14  NFM31PC276B0J3L  [Murata_NFM31P]

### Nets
1P2V_CON: C25.1 J5.1 R16.2 R22.2
1P8V_CON: C24.1 J4.1 R36.2 R44.2
3P3V_CON: C23.1 F1.2 J3.1 J7.2
GND: C23.2 C24.2 C25.2 C26.2 C27.2 C28.2 C29.2 C30.2 C31.2 C32.2 C33.2 C34.2 C35.2 C36.2 C37.2 C38.2 C39.2 C40.2 C41.2 C42.2 C43.2 C44.2 C45.2 C46.2 C47.2 C48.2 C49.2 D1.1(K) D2.1(K) D3.1(K) D4.1(K) D5.1(K) D6.1(K) D7.1(K) D8.1(K) D9.1(K) J3.2 J3.3 J4.2 J4.3 J5.2 J5.3 J6.2 J8.2 R19.1 R25.1 R42.1 R50.1 U6.1(AGND) U6.2(PGND) U7.2 U8.1(AGND) U8.2(PGND) U9.2 U10.8(GND) U10.9(GND) U11.5(BIAS) U11.6(GND) U11.7(GND) U11.12(GND) U12.2 U13.5(BIAS) U13.6(GND) U13.7(GND) U13.12(GND) U14.2
VDD_1P2V_1: U7.3
VDD_1P2V_2: U9.3
VDD_1P8V_1: R43.1 U12.3
VDD_1P8V_2: R51.1 U14.3
VDD_3P3V: C26.1 C27.1 C28.1 C29.1 C30.1 C32.1 C33.1 C36.1 C37.1 C40.1 C45.1 F1.1 J6.1 R15.2 R18.2 R21.1 R24.2 R31.1 R37.1 R40.2 R45.1 R48.2 U6.3(VIN) U6.4(EN) U8.3(VIN) U10.1(VCCA) U10.2(1DIR) U10.3(2DIR) U10.16(VCCB)
EN_1P2V_2: R20.2 R21.2 U8.4(EN)
EN_1P8V: R26.2 R31.2 U11.3(EN) U13.3(EN)
PG_1P2V_1: R18.1 R20.1 R27.1 U6.5(PG)
PG_1P2V_2: R24.1 R26.1 R29.1 U8.5(PG)
PG_1P8V_1: R32.1 R40.1 U11.8(PG)
PG_1P8V_2: R34.1 R48.1 U13.8(PG)
NetC31_1: C31.1 J8.1 R14.2
NetC34_1: C34.1 C35.1 L6.2 R16.1 R17.2 U6.8(VOS) U6.9(FB) U7.1
NetC38_1: C38.1 C39.1 L7.2 R22.1 R23.2 U8.8(VOS) U8.9(FB) U9.1
NetC41_1: C41.1 C42.1 C43.1 R36.1 R39.2 R41.2 U11.10(OUT) U11.11(OUT) U12.1
NetC44_1: C44.1 U11.4(NR/SS)
NetC46_1: C46.1 C47.1 C48.1 R44.1 R47.2 R49.2 U13.10(OUT) U13.11(OUT) U14.1
NetC49_1: C49.1 U13.4(NR/SS)
NetD1_2: D1.2(A) R15.1
NetD2_2: D2.2(A) R17.1
NetD3_2: D3.2(A) R23.1
NetD4_2: D4.2(A) R28.2
NetD5_2: D5.2(A) R30.2
NetD6_2: D6.2(A) R33.2
NetD7_2: D7.2(A) R35.2
NetD8_2: D8.2(A) R41.1
NetD9_2: D9.2(A) R49.1
NetJ7_1: J7.1 R14.1
NetL6_1: L6.1 U6.7(SW)
NetL7_1: L7.1 U8.7(SW)
NetR19_2: R19.2 U6.6(VSET/MODE)
NetR25_2: R25.2 U8.6(VSET/MODE)
NetR27_2: R27.2 U10.4(1A1)
NetR28_1: R28.1 U10.13(1B1)
NetR29_2: R29.2 U10.5(1A2)
NetR30_1: R30.1 U10.12(1B2)
NetR32_2: R32.2 U10.6(2A1)
NetR33_1: R33.1 U10.11(2B1)
NetR34_2: R34.2 U10.7(2A2)
NetR35_1: R35.1 U10.10(2B2)
NetR37_2: R37.2 U11.1(IN) U11.2(IN)
NetR38_1: R38.1 R42.2 U11.9(FB)
NetR38_2: R38.2 R39.1 R43.2
NetR45_2: R45.2 U13.1(IN) U13.2(IN)
NetR46_1: R46.1 R50.2 U13.9(FB)
NetR46_2: R46.2 R47.1 R51.2

Not connected (* = marked no-connect by the designer): U10 14(2~{OE}) 15(1~{OE})

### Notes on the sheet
- Fan Supply
- (near R16) DNP
- (near R21) DNP
- (near R22) DNP
- (near R31) DNP
- (near R36) DNP
- (near R39) DNP
- (near R44) DNP
- (near R47) DNP

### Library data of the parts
C23-C25 C42 C47 = CMP-0006347-2: CAP, CERM, 1 uF, 16 V, +/- 10%, X5R, 0402; Manufacturer: Taiyo Yuden; TaMin_C: -55°C; Polarized: N; SizeAreaWB_mm2: 3; Value1: Unknown; U/M: EA; Value: 1uF; TaMax_C: 85°C; SizeZ_mm: 0.6; SizeX_mm: 1; SizeY_mm: 0.5; Cap_F: 1µF; AEC Category: Q200
C26 = CMP-0009013-2: CAP, CERM, 47 uF, 10 V, +/- 10%, X5R, AEC-Q200 Grade 1, 1206; Manufacturer: MuRata; TaMin_C: -55°C; Polarized: N; SizeAreaWB_mm2: 10.92; Value1: Unknown; U/M: EA; Value: 47uF; TaMax_C: 85°C; SizeZ_mm: 1.8; SizeX_mm: 3.2; SizeY_mm: 1.6; Cap_Case: 1206; SizeArea_mm2: 5.12; AEC Qualified: Y; Cap_F: 47µF; AEC Grade: 1; AEC Category: Q200
C27 = CMP-0008649-2: as C12 on sheet FTDI_USB
C28 C29 C34 C35 C38 C39 = CMP-0006545-2: CAP, CERM, 22 uF, 6.3 V, +/- 20%, X5R, 0402; Manufacturer: MuRata; TaMin_C: -55°C; Polarized: N; SizeAreaWB_mm2: 3; Value1: Unknown; U/M: EA; Value: 22uF; TaMax_C: 85°C; SizeZ_mm: 0.6; SizeY_mm: 0.5; SizeX_mm: 1; Cap_F: 22µF; AEC Category: Q200
C30 C32 C33 C36 C37 C40 C41 C45 C46 = CMP-0084009-1: as C11 on sheet FTDI_USB
C31 = CMP-0008932-2: CAP, CERM, 220 uF, 4 V, +/- 20%, X5R, 1206_190; Manufacturer: MuRata; TaMin_C: -55°C; Polarized: N; SizeAreaWB_mm2: 10.92; Value1: Unknown; U/M: EA; Value: 220uF; TaMax_C: 85°C; SizeZ_mm: 1.9; SizeX_mm: 3.2; SizeY_mm: 1.6; Cap_Case: 1206; SizeArea_mm2: 5.12; Cap_F: 220µF; AEC Category: Q200
C43 C44 C48 C49 = CMP-0006659-2: CAP, CERM, 0.1 uF, 25 V, +/- 10%, X7R, 0402; Manufacturer: MuRata; TaMin_C: -55°C; Polarized: N; SizeAreaWB_mm2: 3; Value1: Unknown; U/M: EA; Value: 0.1uF; TaMax_C: 125°C; SizeZ_mm: 0.6; SizeX_mm: 1; SizeY_mm: 0.5; Cap_F: 100nF; AEC Category: Q200
D1-D9 = CMP-0002920-2: LED, Green, SMD; Manufacturer: LiteOn; Io_A: 30mA; Vr_V: 5V; Tjmax_C: 85°C; Value1: W; Angle: 130; Vf_V: 2V; Type: AlInGaP
F1 = CMP-0003460-2: Fuse, 8 A, 32VAC/VDC, SMD; Manufacturer: Littelfuse; Irating_A: 8A; SizeAreaWB_mm2: 10.92; Interrupt_AC: 50A; VAC_V: 32V; SizeZ_mm: 1.35; SizeX_mm: 3.2; SizeY_mm: 1.6; SizeArea_mm2: 5.12; Rtyp_Ohm: 6.34m; MeltingTyp: 12.95
J3-J5 = CMP-0074931-1: Power Jack, mini, 2.5mm OD, R/A, TH; Manufacturer: Switchcraft; CNHeader: False; Green_Lifecycle: Not Set; Green_REACh: Incomplete
J6-J8 = CMP-0075626-1: Header, 100mil, 2x1, Gold, TH; Manufacturer: Samtec; Pitch_mm: 2.54; Gender: Male; Cert_CSA: Y; CT: False; Row_Count: 1
L6 L7 = CMP-0059748-1: FIXED IND 220NH 7.7A 8 MOHM SMD; Manufacturer: Würth Elektronik; Isat: 8.3A @ 30% inductance drop; Irms: 7.6A @ 40C rise; Green_Lifecycle: Not Set; SizeAreaWB_mm2: 14.7; DCR_ohm: 9m; Green_REACh: Incomplete; Value1: 0.009 ohm; Material: Powdered Iron; Imax_A: 7.6A; SizeZ_mm: 1.2; SizeX_mm: 3.2; SizeY_mm: 2.5; SizeArea_mm2: 8; CompType: Inductor; AEC Qualified: N; AEC Category: Q200
R14 = CMP-0027750-1: RES, 4.70, 1%, 0.05 W, 0201; Manufacturer: Yageo America; Power_W: 50mW; TempCo: 350 ppm/C; Value_Code: 4R70; U/M: EA; Value: 4.70; Res_ohm: 4.7; SizeX_mm: 0.6; SizeY_mm: 0.3; SizeZ_mm: 0.26; Value2: 0.05W; SizeArea_mm2: 0.18; AEC Qualified: N; VDC_V: 25V; AEC Category: Q200
R15 R17 R23 R41 R49 = CMP-0026716-1: RES, 1.00 k, 1%, 0.063 W, 0402; Manufacturer: Rohm; Power_W: 63mW; TempCo: 100 ppm/C; Value_Code: 1k00; U/M: EA; Value: 1.00k; EIA_Code: E96; Res_ohm: 1k; SizeX_mm: 1; SizeY_mm: 0.5; SizeZ_mm: 0.6; Value2: 0.063W; AEC Qualified: N; VDC_V: 50V; AEC Category: Q200
R16 R20-R22 R26 R31 R36 R37 R44 R45 = CMP-0026992-3: RES, 0, 5%, 0.1 W, AEC-Q200 Grade 0, 0402; Manufacturer: Panasonic; Power_W: 100mW; TempCo: 600 ppm/C; Value_Code: 0000; Value: 0; EIA_Code: E24; SizeX_mm: 1; SizeY_mm: 0.5; SizeZ_mm: 0.6; Value2: 0.1W; AEC Qualified: Y; VDC_V: 50V; AEC Category: Q200; SizeAreaWB_mm2: 3
R18 R24 = CMP-0026721-1: RES, 100 k, 1%, 0.0625 W, 0402; Manufacturer: Yageo America; Power_W: 62.5mW; TempCo: 100 ppm/C; U/M: EA; Value: 100k; EIA_Code: E96; SizeX_mm: 1; SizeY_mm: 0.5; SizeZ_mm: 0.6; AEC Qualified: N; VDC_V: 50V; AEC Category: Q200
R19 R25 = CMP-0026453-2: RES, 56.2 k, 1%, 0.063 W, AEC-Q200 Grade 0, 0402; Manufacturer: Vishay-Dale; Power_W: 63mW; TempCo: 100 ppm/C; Value_Code: 56k2; Value: 56.2k; EIA_Code: E96; SizeX_mm: 1; SizeY_mm: 0.5; SizeZ_mm: 0.6; Value2: 0.063W; AEC Qualified: Y; VDC_V: 50V; AEC Category: Q200; AEC Grade: 0
R27 R29 R32 R34 = CMP-0026030-3: RES, 15.0, 1%, 0.063 W, AEC-Q200 Grade 0, 0402; Manufacturer: Vishay-Dale; Power_W: 63mW; TempCo: 100 ppm/C; Value_Code: 15R0; Value: 15.0; EIA_Code: E96; Res_ohm: 15; SizeX_mm: 1; SizeY_mm: 0.5; SizeZ_mm: 0.6; Value2: 0.063W; AEC Qualified: Y; VDC_V: 50V; AEC Category: Q200; AEC Grade: 0
R28 R30 R33 R35 = CMP-0026204-2: RES, 261, 1%, 0.063 W, AEC-Q200 Grade 0, 0402; Manufacturer: Vishay-Dale; Power_W: 63mW; TempCo: 100 ppm/C; Value_Code: 261R; Value: 261; EIA_Code: E96; SizeX_mm: 1; SizeY_mm: 0.5; SizeZ_mm: 0.6; Value2: 0.063W; AEC Qualified: Y; VDC_V: 50V; AEC Category: Q200; AEC Grade: 0
R38 R46 = CMP-0078783-1: RES, 1.87 k, 1%, 0.063 W, 0402; Manufacturer: Yageo America; Value_Code: 1k87; SizeArea_mm2: 0.5; AEC Qualified: N; AEC Category: Q200; Value: 1.87k; SizeZ_mm: 0.6; EIA_Code: E96; TempCo: 100 ppm/C; Power_W: 63mW; VDC_V: 50V; Value2: 0.063W; SizeX_mm: 1
R39 R43 R47 R51 = CMP-0026271-2: as R2 on sheet FTDI_USB
R40 R48 = CMP-0026383-2: RES, 44.2 k, 1%, 0.063 W, AEC-Q200 Grade 0, 0402; Manufacturer: Vishay-Dale; Power_W: 63mW; TempCo: 100 ppm/C; Value_Code: 44k2; Value: 44.2k; EIA_Code: E96; SizeX_mm: 1; SizeY_mm: 0.5; SizeZ_mm: 0.6; Value2: 0.063W; AEC Qualified: Y; VDC_V: 50V; AEC Category: Q200; AEC Grade: 0
R42 R50 = CMP-0026088-3: RES, 1.50 k, 1%, 0.063 W, AEC-Q200 Grade 0, 0402; Manufacturer: Vishay-Dale; Power_W: 63mW; TempCo: 100 ppm/C; Value_Code: 1k50; Value: 1.50k; EIA_Code: E96; Res_ohm: 1.5k; SizeX_mm: 1; SizeY_mm: 0.5; SizeZ_mm: 0.6; Value2: 0.063W; AEC Qualified: Y; VDC_V: 50V; AEC Category: Q200; AEC Grade: 0
U6 U8 = CMP-0089105-4: 2.4-V to 5.5-V Input, 6-A Step-Down Converter in 1.5-mm x 2.5-mm QFN Package; Manufacturer: Texas Instruments; SizeZ_mm: 1mm; Number Of Outputs: 1; AEC Qualified: No; Switching Topology: Buck; Switching Frequency: 2.4MHz; Output Type: Fixed,AdjustableProgrammable; CompType: IC; Max Duty Cycle: 100%; Max Supply Voltage: 5.5V; Standoff Height: 0mm; Min Supply Voltage: 2.4V; Nominal Supply Current: 4uA; TJmax_C: +125°C; AEC Category: Q200
U7 U9 U12 U14 = CMP-0001934-2: FILTER LC HIGH FREQ 27uF 1206; Manufacturer: MuRata
U10 = CMP-0066448-2: 4-Bit Dual-Supply Bus Transceiver with Configurable Voltage-Level Shifting and 3-State Outputs, PW0016A (TSSOP-16); Alternate Manufacturer: Texas Instruments; Green_Lifecycle: Active; SizeAreaWB_mm2: 58.8; Green_REACh: Passed; SizeZ_mm: 1.2; SizeX_mm: 6.4; SizeY_mm: 5.0; SizeArea_mm2: 32.0; CompType: IC; AEC Category: Q200; AEC Qualified: N
U11 U13 = CMP-0860539-1: 3-A, High-Accuracy (0.75%), Low-Noise (4.4μVRMS), LDO Voltage Regulator, RPS0012A (VQFN-12); Alternate Manufacturer: Texas Instruments; SizeZ_mm: 1; SizeX_mm: 2.2; AEC Category: Q200; CompType: IC; SizeAreaWB_mm2: 11.2; SizeY_mm: 2.5; SizeArea_mm2: 5.5; AEC Qualified: N

## Sheet DF410_Ingress_1.SchDoc: Retimer Ingress RX1-4
size A2; Date: Not shown in title block; ApprovedBy: Not shown in title block; CheckedBy: Not shown in title block; Author: Not shown in title block; CompanyName: Not shown in title block; Engineer: Not shown in title block; Organization: Not shown in title block; Address1: Not shown in title block; Address2: Not shown in title block; Address3: Not shown in title block; Address4: Not shown in title block; DocumentNumber: 1; Revision: Use project parameter SCH_Rev; SheetNumber: 1; SheetTotal: 1; PageSetup: Record=PageOptions¦CenterHorizontal=True¦CenterVertical=True¦PrintScale=0.69¦XCorrection=1.00¦YCorrection=1.00¦PrintKind=0¦BorderSize=5000000¦LeftOffset=0¦BottomOffset=0¦Orientation=2¦PaperLength=1000¦PaperWidth=1000¦Scale=100¦PaperSource=15¦PrintQuality=600¦MediaType=1¦DitherType=10¦PaperKind=Letter¦PrintScaleMode=1
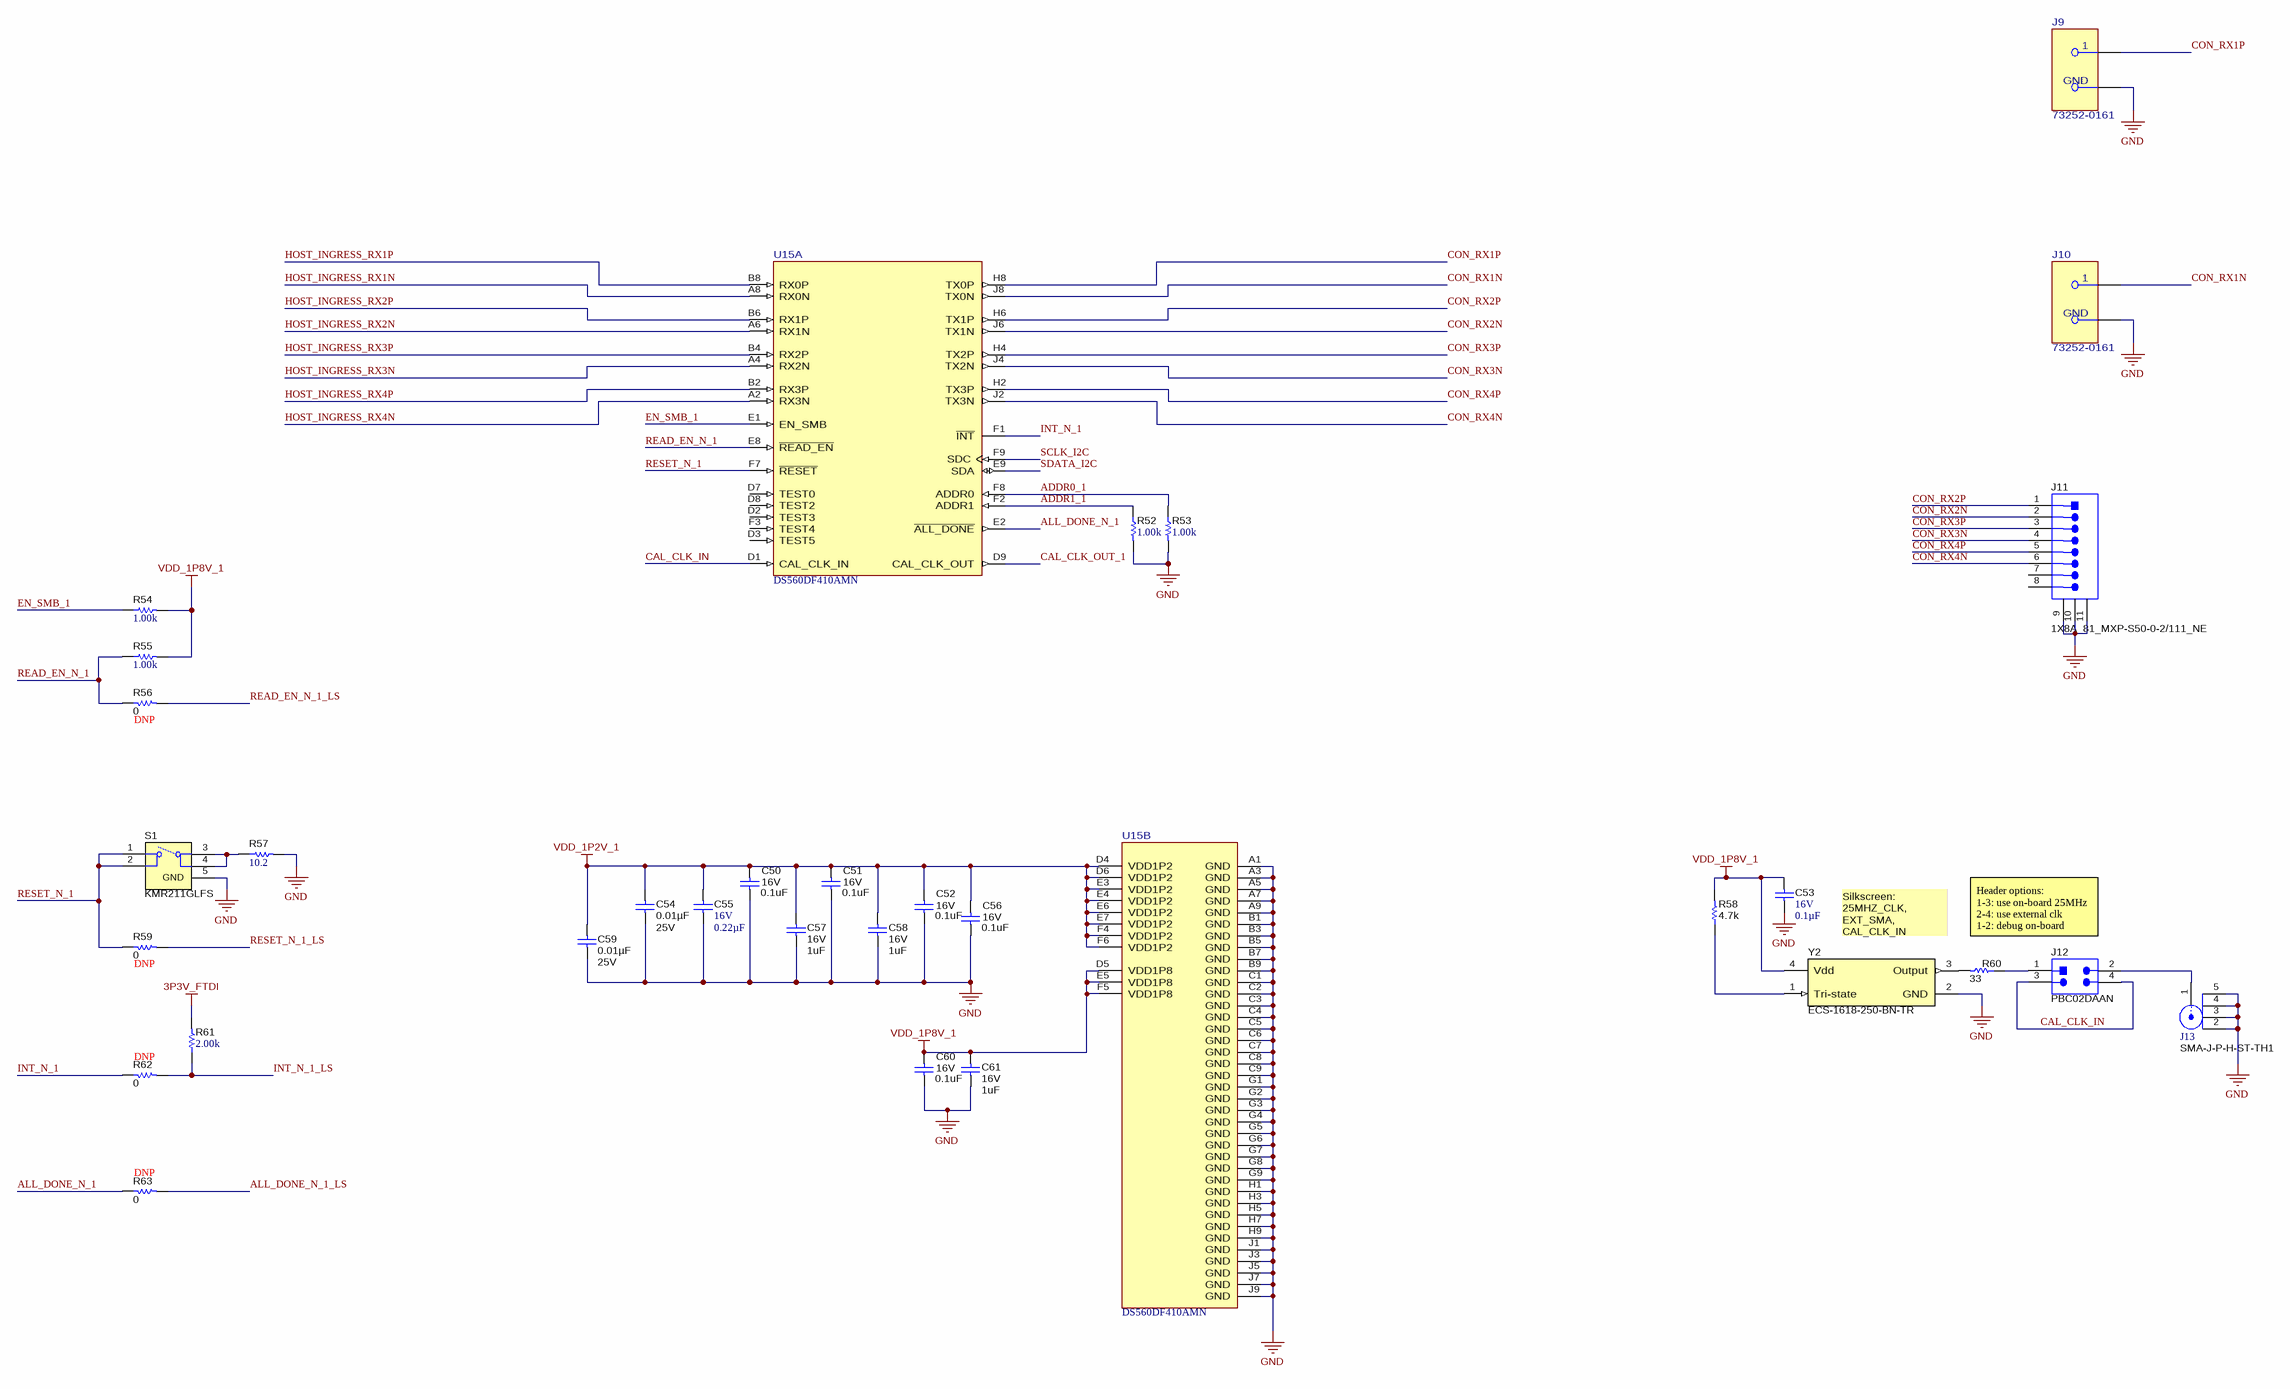
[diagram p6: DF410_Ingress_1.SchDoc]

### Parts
C50  Value2: 16V  ValueDisplayed: 0.1uF  [0201_033]  (hidden comment: GRM033C71C104KE14D)
C51  Value2: 16V  ValueDisplayed: 0.1uF  [0201_033]  (hidden comment: GRM033C71C104KE14D)
C52  Value2: 16V  ValueDisplayed: 0.1uF  [0201_033]  (hidden comment: GRM033C71C104KE14D)
C53  VDC_V: 16V  ValueDisplayed: 0.1µF  [0402]  (hidden comment: EMK105B7104KV-F)
C54  ValueDisplayed: 0.01µF  VDC_V: 25V  [0201_033]  (hidden comment: GRM033R61E103KA12D)
C55  VDC_V: 16V  ValueDisplayed: 0.22µF  [0402]  (hidden comment: CL05B224KO5NNNC)
C56  Value2: 16V  ValueDisplayed: 0.1uF  [0201_033]  (hidden comment: GRM033C71C104KE14D)
C57  VDC_V: 16V  ValueDisplayed: 1uF  [0603]  (hidden comment: GRM188R61C105KA93D)
C58  VDC_V: 16V  ValueDisplayed: 1uF  [0603]  (hidden comment: GRM188R61C105KA93D)
C59  ValueDisplayed: 0.01µF  VDC_V: 25V  [0201_033]  (hidden comment: GRM033R61E103KA12D)
C60  Value2: 16V  ValueDisplayed: 0.1uF  [0201_033]  (hidden comment: GRM033C71C104KE14D)
C61  VDC_V: 16V  ValueDisplayed: 1uF  [0603]  (hidden comment: GRM188R61C105KA93D)
J9  73252-0161  [FP-73252-0161_CONN_RF_JACK-MFG]
J10  73252-0161  [FP-73252-0161_CONN_RF_JACK-MFG]
J11  1X8A_81_MXP-S50-0-2/111_NE  [H+S_1x8A_81_MXP-S50-0-2_111N]
J12  PBC02DAAN  [Sullins_PxC02DAAN]
J13  SMA-J-P-H-ST-TH1  [SAMTEC_SMA-J-P-H-ST-TH1]
R52  ValueDisplayed: 1.00k  [0402]  (hidden comment: CRCW04021K00FKED)
R53  ValueDisplayed: 1.00k  [0402]  (hidden comment: CRCW04021K00FKED)
R54  ValueDisplayed: 1.00k  [0402]  (hidden comment: CRCW04021K00FKED)
R55  ValueDisplayed: 1.00k  [0402]  (hidden comment: CRCW04021K00FKED)
R56  ValueDisplayed: 0  [0402]  (hidden comment: ERJ-2GE0R00X)
R57  ValueDisplayed: 10.2  [0402]  (hidden comment: CRCW040210R2FKED)
R58  ValueDisplayed: 4.7k  [0402]  (hidden comment: CRCW04024K70JNED)
R59  ValueDisplayed: 0  [0402]  (hidden comment: ERJ-2GE0R00X)
R60  value 33  [0402]  (hidden comment: Resistor)
R61  ValueDisplayed: 2.00k  [0402]  (hidden comment: ERJ-2RKF2001X)
R62  ValueDisplayed: 0  [0402]  (hidden comment: ERJ-2GE0R00X)
R63  ValueDisplayed: 0  [0402]  (hidden comment: ERJ-2GE0R00X)
S1  KMR211GLFS  [SW_KMR211GLFS]
U15  DS560DF410AMN  [AMN0081A-MFG]  (parts A,B of 2)
Y2  ECS-1618-250-BN-TR  [ECS-1618-250-BN-TR]

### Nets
3P3V_FTDI: R61.2
GND: C50.2 C51.2 C52.2 C53.2 C54.2 C55.2 C56.2 C57.2 C58.2 C59.2 C60.2 C61.2 J9.2(GND) J10.2(GND) J11.9 J11.10 J11.11 J13.2 J13.3 J13.4 J13.5 R52.2 R53.2 R57.2 S1.5(GND) U15.A1(GND) U15.A3(GND) U15.A5(GND) U15.A7(GND) U15.A9(GND) U15.B1(GND) U15.B3(GND) U15.B5(GND) U15.B7(GND) U15.B9(GND) U15.C1(GND) U15.C2(GND) U15.C3(GND) U15.C4(GND) U15.C5(GND) U15.C6(GND) U15.C7(GND) U15.C8(GND) U15.C9(GND) U15.G1(GND) U15.G2(GND) U15.G3(GND) U15.G4(GND) U15.G5(GND) U15.G6(GND) U15.G7(GND) U15.G8(GND) U15.G9(GND) U15.H1(GND) U15.H3(GND) U15.H5(GND) U15.H7(GND) U15.H9(GND) U15.J1(GND) U15.J3(GND) U15.J5(GND) U15.J7(GND) U15.J9(GND) Y2.2(GND)
VDD_1P2V_1: C50.1 C51.1 C52.1 C54.1 C55.1 C56.1 C57.1 C58.1 C59.1 U15.D4(VDD1P2) U15.D6(VDD1P2) U15.E3(VDD1P2) U15.E4(VDD1P2) U15.E6(VDD1P2) U15.E7(VDD1P2) U15.F4(VDD1P2) U15.F6(VDD1P2)
VDD_1P8V_1: C53.1 C60.1 C61.1 R54.2 R55.2 R58.2 U15.D5(VDD1P8) U15.E5(VDD1P8) U15.F5(VDD1P8) Y2.4(Vdd)
ADDR0_1: R53.1 U15.F8(ADDR0)
ADDR1_1: R52.1 U15.F2(ADDR1)
ALL_DONE_N_1: R63.1 U15.E2(~{ALL_DONE})
ALL_DONE_N_1_LS: R63.2
CAL_CLK_IN: J12.3 J12.4 U15.D1(CAL_CLK_IN)
CAL_CLK_OUT_1: U15.D9(CAL_CLK_OUT)
CON_RX1N: J10.1 U15.J8(TX0N)
CON_RX1P: J9.1 U15.H8(TX0P)
CON_RX2N: J11.2 U15.J6(TX1N)
CON_RX2P: J11.1 U15.H6(TX1P)
CON_RX3N: J11.4 U15.J4(TX2N)
CON_RX3P: J11.3 U15.H4(TX2P)
CON_RX4N: J11.6 U15.J2(TX3N)
CON_RX4P: J11.5 U15.H2(TX3P)
EN_SMB_1: R54.1 U15.E1(EN_SMB)
HOST_INGRESS_RX1N: U15.A8(RX0N)
HOST_INGRESS_RX1P: U15.B8(RX0P)
HOST_INGRESS_RX2N: U15.A6(RX1N)
HOST_INGRESS_RX2P: U15.B6(RX1P)
HOST_INGRESS_RX3N: U15.A4(RX2N)
HOST_INGRESS_RX3P: U15.B4(RX2P)
HOST_INGRESS_RX4N: U15.A2(RX3N)
HOST_INGRESS_RX4P: U15.B2(RX3P)
INT_N_1: R62.1 U15.F1(~{INT})
INT_N_1_LS: R61.1 R62.2
READ_EN_N_1: R55.1 R56.1 U15.E8(~{READ_EN})
READ_EN_N_1_LS: R56.2
RESET_N_1: R59.1 S1.1 S1.2 U15.F7(~{RESET})
RESET_N_1_LS: R59.2
SCLK_I2C: U15.F9(SDC)
SDATA_I2C: U15.E9(SDA)
NetJ12_1: J12.1 R60.1
NetJ12_2: J12.2 J13.1
NetR57_1: R57.1 S1.3 S1.4
NetR58_1: R58.1 Y2.1(Tri-state)
NetR60_2: R60.2 Y2.3(Output)

Not connected (* = marked no-connect by the designer): J11 7 8; U15 D2(TEST3) D3(TEST5) D7(TEST0) D8(TEST2) F3(TEST4)

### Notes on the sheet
- (near R56) DNP
- (near R59) DNP
- Silkscreen: 25MHZ_CLK, EXT_SMA, CAL_CLK_IN
- Header options:
  1-3: use on-board 25MHz
  2-4: use external clk
  1-2: debug on-board 25MHz
- (near R62) DNP
- (near R63) DNP

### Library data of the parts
C50-C52 C56 C60 = CMP-0009670-3: CAP, CERM, 0.1 uF, 16 V, +/- 10%, X5R, 0201; Manufacturer: MuRata; TaMin_C: -55°C; Polarized: N; SizeAreaWB_mm2: 2.08; Value1: Unknown; U/M: EA; Value: 0.1uF; TaMax_C: 125°C; SizeZ_mm: 0.33; SizeX_mm: 0.6; SizeY_mm: 0.3; Cap_Case: 0201; SizeArea_mm2: 0.18; Cap_F: 100nF; AEC Category: Q200
C53 = CMP-0860188-1: as C2 on sheet FTDI_USB
C54 C59 = CMP-0086060-1: CAP, CERM, 0.01 µF, 25 V,+/- 10%, X5R, 0201; Manufacturer: MuRata; SizeY_mm: 0.3; SizeZ_mm: 0.33; SizeAreaWB_mm2: 2.08; U/M: EA; AEC Category: Q200; SizeX_mm: 0.6; TaMin_C: -55°C; Polarized: N; TaMax_C: 85°C; Value: 0.01uF; Cap_F: 10nF; SizeArea_mm2: 0.18; Cap_Case: 0201
C55 = CMP-0860563-1: CAP, CERM, 0.22 µF, 16 V,+/- 10%, X7R, 0402; Manufacturer: Samsung Electro-Mechanics; TaMin_C: -55°C; Polarized: N; SizeAreaWB_mm2: 3; U/M: EA; Value: 0.22uF; TaMax_C: 125°C; SizeZ_mm: 0.6; SizeX_mm: 1; SizeY_mm: 0.5; Cap_F: 220nF; AEC Category: Q200; Green_Lifecycle: Active; Green_REACh: Incomplete
C57 C58 C61 = CMP-0007335-5: CAP, CERM, 1 uF, 16 V, +/- 10%, X5R, 0603; Manufacturer: MuRata; TaMin_C: -55°C; Polarized: N; SizeAreaWB_mm2: 4.68; Value1: Unknown; U/M: EA; Value: 1uF; TaMax_C: 85°C; SizeZ_mm: 1; SizeX_mm: 1.6; SizeY_mm: 0.8; SizeArea_mm2: 1.28; Cap_F: 1µF; AEC Category: Q200
J9 J10 = CMP-0097248-1: 2.92MM JACK,PCB,COMPRESSION W/SL; Manufacturer: Molex; Is Female: yes; Conn Orientation: Vertical; Dielectric Material: PTFE; ContactFinish: Gold,Nickel; SizeZ_mm: 11.17mm; AEC Qualified: No
J11 = CMP-0074975-2: Straight PCB plug Pin-in-hole/SMT; Manufacturer: Huber+Suhner; CT: False; Green_REACh: Incomplete; Green_Lifecycle: Not Set
J12 = CMP-0054598-1: Header, 2.54mm, 2x2, Gold, TH; Manufacturer: Sullins Connector Solutions; CNHeader: TRUE; Current_A: 3A; Shrouded: N; Gender: Male; Voltage_V: 1.8kV; Row_Count: 2; RowSpacing_mm: 2.54; CT: FALSE; Cert_UL: Y
J13 = CMP-0075495-1: SMA Jack, Straight, 50 Ohm, Gold, TH; Manufacturer: Samtec; Green_REACh: Incomplete; CT: True; Green_Lifecycle: Not Set; CNHeader: False
R52-R55 = CMP-0026071-3: as R8 on sheet FTDI_USB
R56 R59 R62 R63 = CMP-0026992-3: as R16 on sheet PWR_Supplies
R57 = CMP-0025964-3: RES, 10.2, 1%, 0.063 W, AEC-Q200 Grade 0, 0402; Manufacturer: Vishay-Dale; Power_W: 63mW; TempCo: 100 ppm/C; Value_Code: 10R2; Value: 10.2; EIA_Code: E96; SizeX_mm: 1; SizeY_mm: 0.5; SizeZ_mm: 0.6; Value2: 0.063W; AEC Qualified: Y; VDC_V: 50V; AEC Category: Q200; AEC Grade: 0
R58 = CMP-0026938-5: RES, 4.7 k, 5%, 0.063 W, AEC-Q200 Grade 0, 0402; Manufacturer: Vishay-Dale; Power_W: 63mW; TempCo: 200 ppm/C; Value_Code: 4k70; Value: 4.7k; EIA_Code: E24; SizeX_mm: 1; SizeY_mm: 0.5; SizeZ_mm: 0.6; Value2: 0.063W; AEC Qualified: Y; VDC_V: 50V; AEC Category: Q200; AEC Grade: 0
R60 = CMP-0026908-3: RES, 33, 5%, 0.063 W, AEC-Q200 Grade 0, 0402; PartNumber: CRCW040233R0JNED; Manufacturer: Vishay-Dale; Value_Code: 33R0; Power_W: 63mW; Value2: 0.063W; VDC_V: 50V; TempCo: 200 ppm/C; EIA_Code: E24; AEC Category: Q200; AEC Grade: 0; AEC Qualified: Y; SizeArea_mm2: 0.5; SizeX_mm: 1; SizeZ_mm: 0.6
R61 = CMP-0026676-1: as R1 on sheet FTDI_USB
S1 = CMP-0002322-1: Switch, SPST-NO, Off-Mom, 0.05 A, 32 VDC, SMD; Manufacturer: C&K Components; CurrentRating_mA: 50A; PositionCount: 1; SizeX_mm: 4.6; SizeY_mm: 2.8; SizeZ_mm: 1.9; SizeArea_mm2: 12.88; VDC_V: 32V; SizeAreaWB_mm2: 21.28
U15 = CMP-0095008-2: 56 Gbps Multi-Rate 4-Channel Retimer with Crosspoint; Manufacturer: Texas Instruments; AEC Category: Q200; TaMin_C: -40°C; AEC Qualified: No; SizeZ_mm: 1.225mm; Standoff Height: 0.261mm; TJmax_C: +110°C; Data Rate: 56Gbits/s; Min Supply Voltage: 1.15V; Max Supply Voltage: 1.85V; CompType: IC; TaMax_C: +85°C; Interface: I2C,SMBus,Other
Y2 = SYM-ASCO-25.000MHZ-EK-T3: XTAL OSC XO 25.0000MHZ CMOS SMD; Manufacturer: ECS Inc.; AEC Qualified: No; Max Supply Current: 4.2mA; Min Supply Voltage: 2.97V; Frequency Stability: 50ppm; Max Supply Voltage: 3.63V; Frequency_Fixed: 25MHz; Load Capacitance: 15pF

## Sheet DF410_Ingress_2.SchDoc: Retimer Ingress RX5-8
size A2; Date: Not shown in title block; ApprovedBy: Not shown in title block; CheckedBy: Not shown in title block; Author: Not shown in title block; CompanyName: Not shown in title block; Engineer: Not shown in title block; Organization: Not shown in title block; Address1: Not shown in title block; Address2: Not shown in title block; Address3: Not shown in title block; Address4: Not shown in title block; DocumentNumber: 1; Revision: Use project parameter SCH_Rev; SheetNumber: 1; SheetTotal: 1; PageSetup: Record=PageOptions¦CenterHorizontal=True¦CenterVertical=True¦PrintScale=0.69¦XCorrection=1.00¦YCorrection=1.00¦PrintKind=0¦BorderSize=5000000¦LeftOffset=0¦BottomOffset=0¦Orientation=2¦PaperLength=1000¦PaperWidth=1000¦Scale=100¦PaperSource=15¦PrintQuality=600¦MediaType=1¦DitherType=10¦PaperKind=Letter¦PrintScaleMode=1
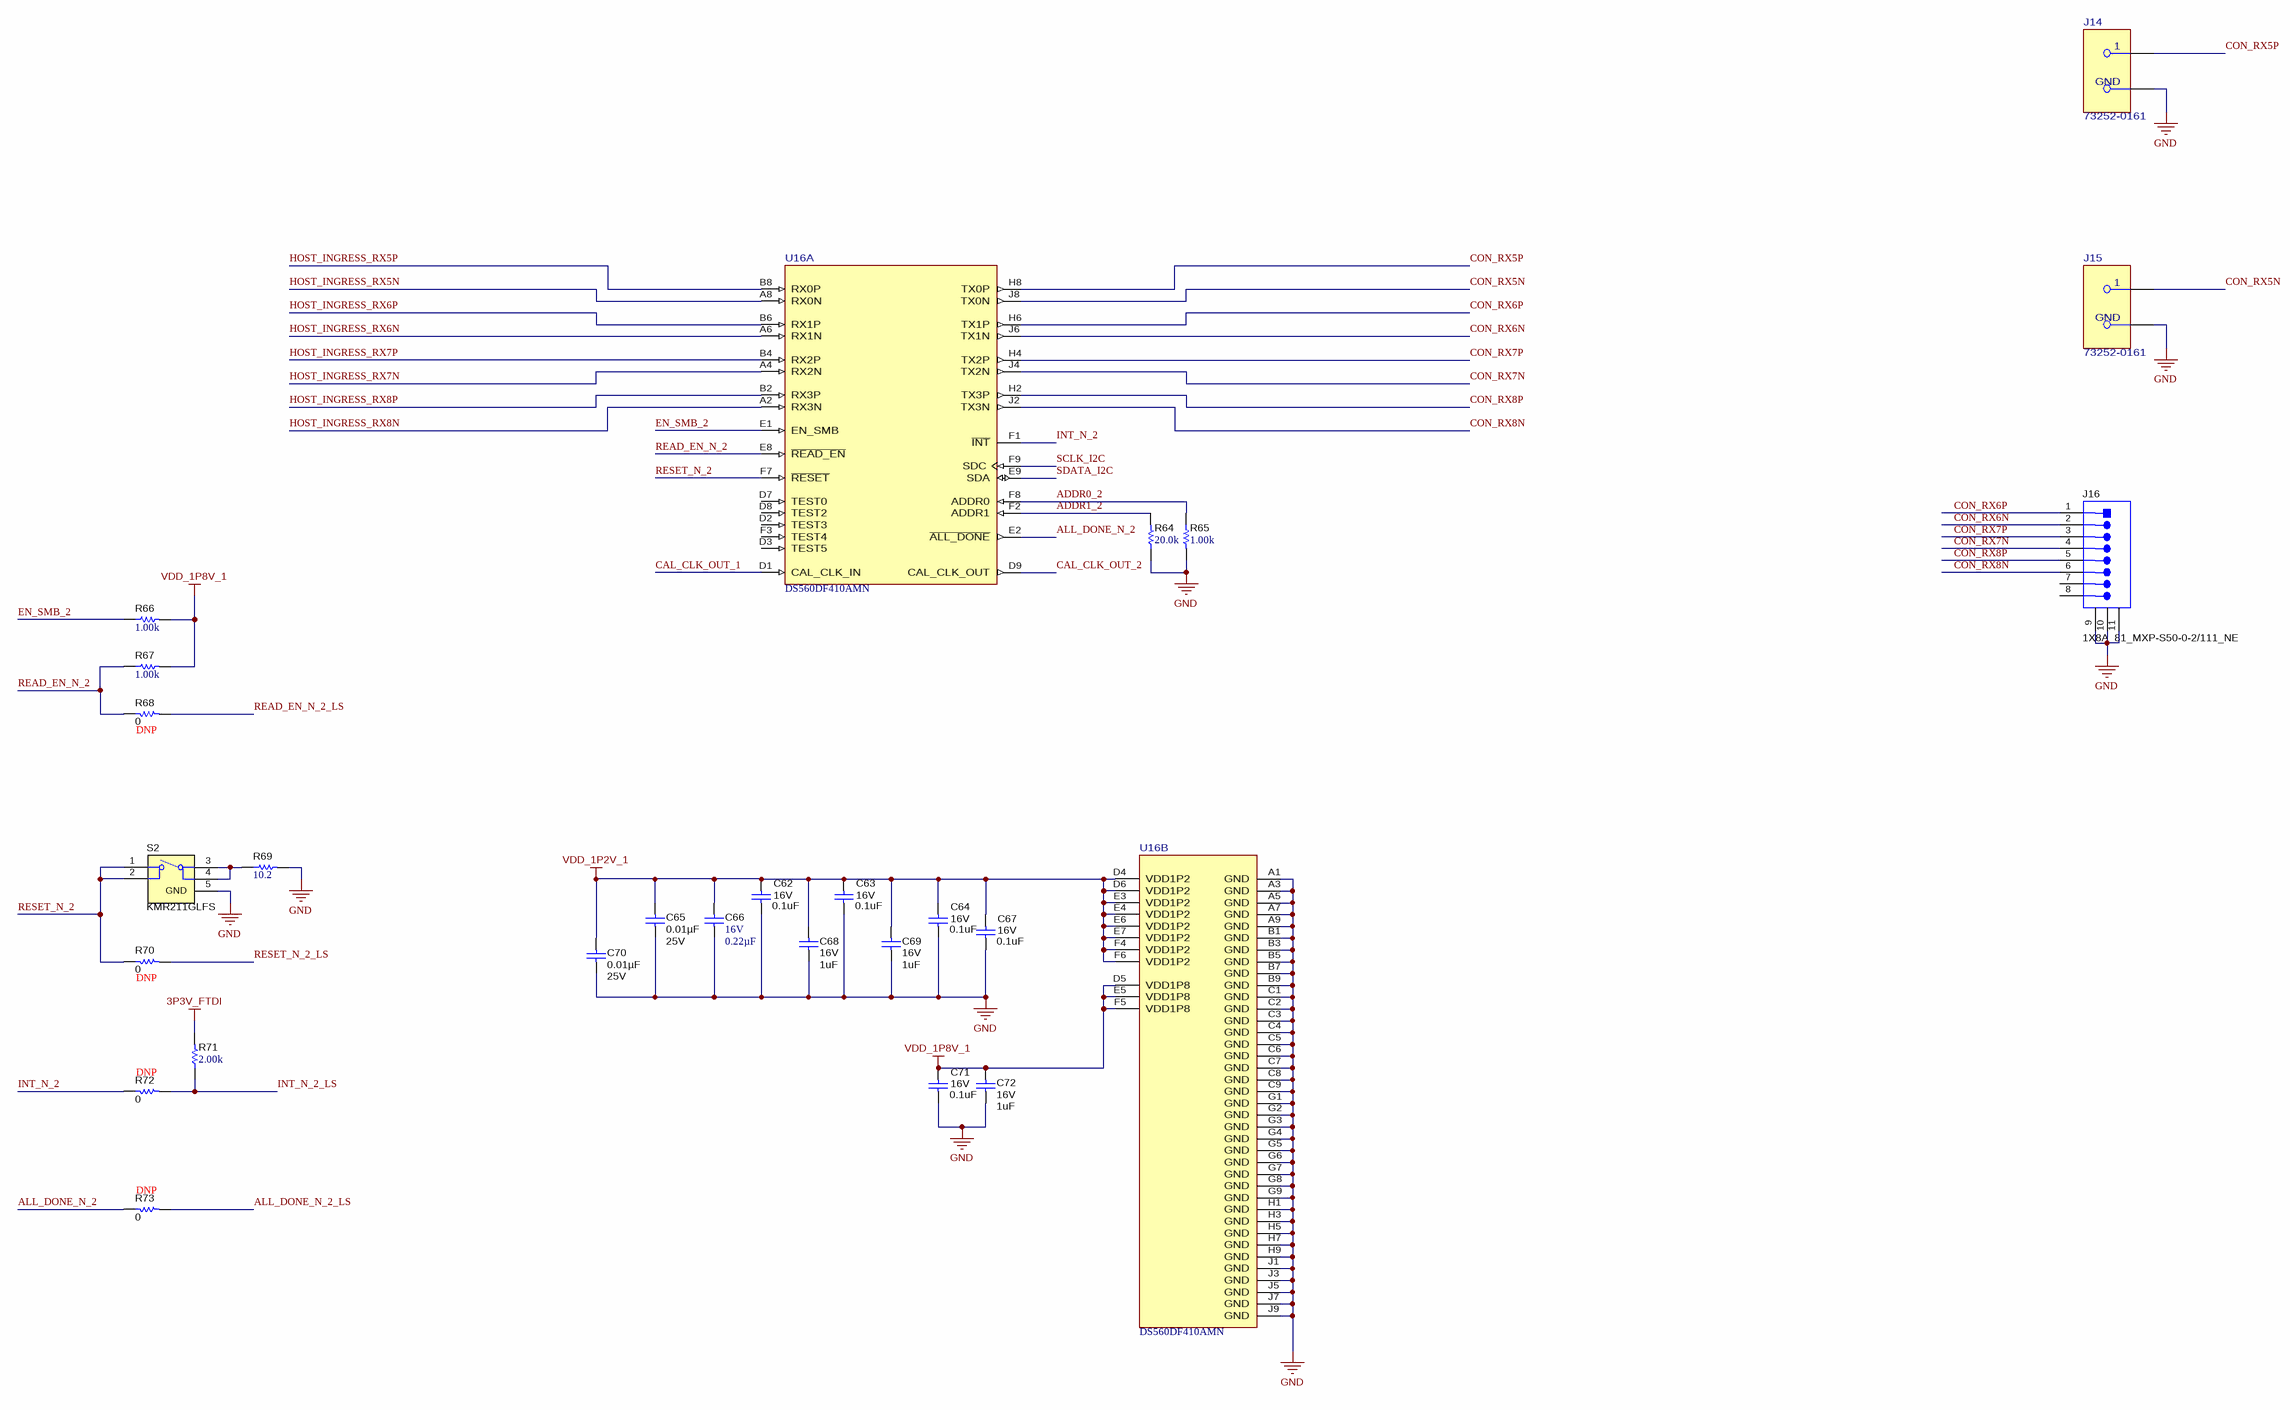
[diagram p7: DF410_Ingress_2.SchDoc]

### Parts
C62  Value2: 16V  ValueDisplayed: 0.1uF  [0201_033]  (hidden comment: GRM033C71C104KE14D)
C63  Value2: 16V  ValueDisplayed: 0.1uF  [0201_033]  (hidden comment: GRM033C71C104KE14D)
C64  Value2: 16V  ValueDisplayed: 0.1uF  [0201_033]  (hidden comment: GRM033C71C104KE14D)
C65  ValueDisplayed: 0.01µF  VDC_V: 25V  [0201_033]  (hidden comment: GRM033R61E103KA12D)
C66  VDC_V: 16V  ValueDisplayed: 0.22µF  [0402]  (hidden comment: CL05B224KO5NNNC)
C67  Value2: 16V  ValueDisplayed: 0.1uF  [0201_033]  (hidden comment: GRM033C71C104KE14D)
C68  VDC_V: 16V  ValueDisplayed: 1uF  [0603]  (hidden comment: GRM188R61C105KA93D)
C69  VDC_V: 16V  ValueDisplayed: 1uF  [0603]  (hidden comment: GRM188R61C105KA93D)
C70  ValueDisplayed: 0.01µF  VDC_V: 25V  [0201_033]  (hidden comment: GRM033R61E103KA12D)
C71  Value2: 16V  ValueDisplayed: 0.1uF  [0201_033]  (hidden comment: GRM033C71C104KE14D)
C72  VDC_V: 16V  ValueDisplayed: 1uF  [0603]  (hidden comment: GRM188R61C105KA93D)
J14  73252-0161  [FP-73252-0161_CONN_RF_JACK-MFG]
J15  73252-0161  [FP-73252-0161_CONN_RF_JACK-MFG]
J16  1X8A_81_MXP-S50-0-2/111_NE  [H+S_1x8A_81_MXP-S50-0-2_111N]
R64  ValueDisplayed: 20.0k  [0402]  (hidden comment: PCF0402-12-20K0BT1)
R65  ValueDisplayed: 1.00k  [0402]  (hidden comment: CRCW04021K00FKED)
R66  ValueDisplayed: 1.00k  [0402]  (hidden comment: CRCW04021K00FKED)
R67  ValueDisplayed: 1.00k  [0402]  (hidden comment: CRCW04021K00FKED)
R68  ValueDisplayed: 0  [0402]  (hidden comment: ERJ-2GE0R00X)
R69  ValueDisplayed: 10.2  [0402]  (hidden comment: CRCW040210R2FKED)
R70  ValueDisplayed: 0  [0402]  (hidden comment: ERJ-2GE0R00X)
R71  ValueDisplayed: 2.00k  [0402]  (hidden comment: ERJ-2RKF2001X)
R72  ValueDisplayed: 0  [0402]  (hidden comment: ERJ-2GE0R00X)
R73  ValueDisplayed: 0  [0402]  (hidden comment: ERJ-2GE0R00X)
S2  KMR211GLFS  [SW_KMR211GLFS]
U16  DS560DF410AMN  [AMN0081A-MFG]  (parts A,B of 2)

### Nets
3P3V_FTDI: R71.2
GND: C62.2 C63.2 C64.2 C65.2 C66.2 C67.2 C68.2 C69.2 C70.2 C71.2 C72.2 J14.2(GND) J15.2(GND) J16.9 J16.10 J16.11 R64.1 R65.2 R69.2 S2.5(GND) U16.A1(GND) U16.A3(GND) U16.A5(GND) U16.A7(GND) U16.A9(GND) U16.B1(GND) U16.B3(GND) U16.B5(GND) U16.B7(GND) U16.B9(GND) U16.C1(GND) U16.C2(GND) U16.C3(GND) U16.C4(GND) U16.C5(GND) U16.C6(GND) U16.C7(GND) U16.C8(GND) U16.C9(GND) U16.G1(GND) U16.G2(GND) U16.G3(GND) U16.G4(GND) U16.G5(GND) U16.G6(GND) U16.G7(GND) U16.G8(GND) U16.G9(GND) U16.H1(GND) U16.H3(GND) U16.H5(GND) U16.H7(GND) U16.H9(GND) U16.J1(GND) U16.J3(GND) U16.J5(GND) U16.J7(GND) U16.J9(GND)
VDD_1P2V_1: C62.1 C63.1 C64.1 C65.1 C66.1 C67.1 C68.1 C69.1 C70.1 U16.D4(VDD1P2) U16.D6(VDD1P2) U16.E3(VDD1P2) U16.E4(VDD1P2) U16.E6(VDD1P2) U16.E7(VDD1P2) U16.F4(VDD1P2) U16.F6(VDD1P2)
VDD_1P8V_1: C71.1 C72.1 R66.2 R67.2 U16.D5(VDD1P8) U16.E5(VDD1P8) U16.F5(VDD1P8)
ADDR0_2: R65.1 U16.F8(ADDR0)
ADDR1_2: R64.2 U16.F2(ADDR1)
ALL_DONE_N_2: R73.1 U16.E2(~{ALL_DONE})
ALL_DONE_N_2_LS: R73.2
CAL_CLK_OUT_1: U16.D1(CAL_CLK_IN)
CAL_CLK_OUT_2: U16.D9(CAL_CLK_OUT)
CON_RX5N: J15.1 U16.J8(TX0N)
CON_RX5P: J14.1 U16.H8(TX0P)
CON_RX6N: J16.2 U16.J6(TX1N)
CON_RX6P: J16.1 U16.H6(TX1P)
CON_RX7N: J16.4 U16.J4(TX2N)
CON_RX7P: J16.3 U16.H4(TX2P)
CON_RX8N: J16.6 U16.J2(TX3N)
CON_RX8P: J16.5 U16.H2(TX3P)
EN_SMB_2: R66.1 U16.E1(EN_SMB)
HOST_INGRESS_RX5N: U16.A8(RX0N)
HOST_INGRESS_RX5P: U16.B8(RX0P)
HOST_INGRESS_RX6N: U16.A6(RX1N)
HOST_INGRESS_RX6P: U16.B6(RX1P)
HOST_INGRESS_RX7N: U16.A4(RX2N)
HOST_INGRESS_RX7P: U16.B4(RX2P)
HOST_INGRESS_RX8N: U16.A2(RX3N)
HOST_INGRESS_RX8P: U16.B2(RX3P)
INT_N_2: R72.1 U16.F1(~{INT})
INT_N_2_LS: R71.1 R72.2
READ_EN_N_2: R67.1 R68.1 U16.E8(~{READ_EN})
READ_EN_N_2_LS: R68.2
RESET_N_2: R70.1 S2.1 S2.2 U16.F7(~{RESET})
RESET_N_2_LS: R70.2
SCLK_I2C: U16.F9(SDC)
SDATA_I2C: U16.E9(SDA)
NetR69_1: R69.1 S2.3 S2.4

Not connected (* = marked no-connect by the designer): J16 7 8; U16 D2(TEST3) D3(TEST5) D7(TEST0) D8(TEST2) F3(TEST4)

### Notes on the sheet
- (near R68) DNP
- (near R70) DNP
- (near R72) DNP
- (near R73) DNP

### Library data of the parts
C62-C64 C67 C71 = CMP-0009670-3: as C50 on sheet DF410_Ingress_1
C65 C70 = CMP-0086060-1: as C54 on sheet DF410_Ingress_1
C66 = CMP-0860563-1: as C55 on sheet DF410_Ingress_1
C68 C69 C72 = CMP-0007335-5: as C57 on sheet DF410_Ingress_1
J14 J15 = CMP-0097248-1: as J9 on sheet DF410_Ingress_1
J16 = CMP-0074975-2: as J11 on sheet DF410_Ingress_1
R64 = CMP-0026801-1: RES, 20.0 k, 0.1%, 0.063 W, 0402; Manufacturer: TT Electronics/IRC; Power_W: 63mW; TempCo: 10 ppm/C; Value_Code: 20k0; U/M: EA; Value: 20.0k; EIA_Code: E192; Res_ohm: 20k; SizeX_mm: 1; SizeY_mm: 0.5; SizeZ_mm: 0.6; Value2: 0.063W; AEC Qualified: N; VDC_V: 25V; AEC Category: Q200
R65-R67 = CMP-0026071-3: as R8 on sheet FTDI_USB
R68 R70 R72 R73 = CMP-0026992-3: as R16 on sheet PWR_Supplies
R69 = CMP-0025964-3: as R57 on sheet DF410_Ingress_1
R71 = CMP-0026676-1: as R1 on sheet FTDI_USB
S2 = CMP-0002322-1: as S1 on sheet DF410_Ingress_1
U16 = CMP-0095008-2: as U15 on sheet DF410_Ingress_1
